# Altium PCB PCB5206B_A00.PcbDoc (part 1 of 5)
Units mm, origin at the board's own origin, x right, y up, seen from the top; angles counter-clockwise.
Board outline 115 x 60 mm, 6 copper layers (Top Layer, GND Layer 2, Signal Layer 3, Signal Layer 4, VCC Layer 5, Bottom Layer), stack 1.555 mm thick; 384 components, 267 nets, 1313 pads, 834 vias.
Unrouted connection lines stored in the file: 10.
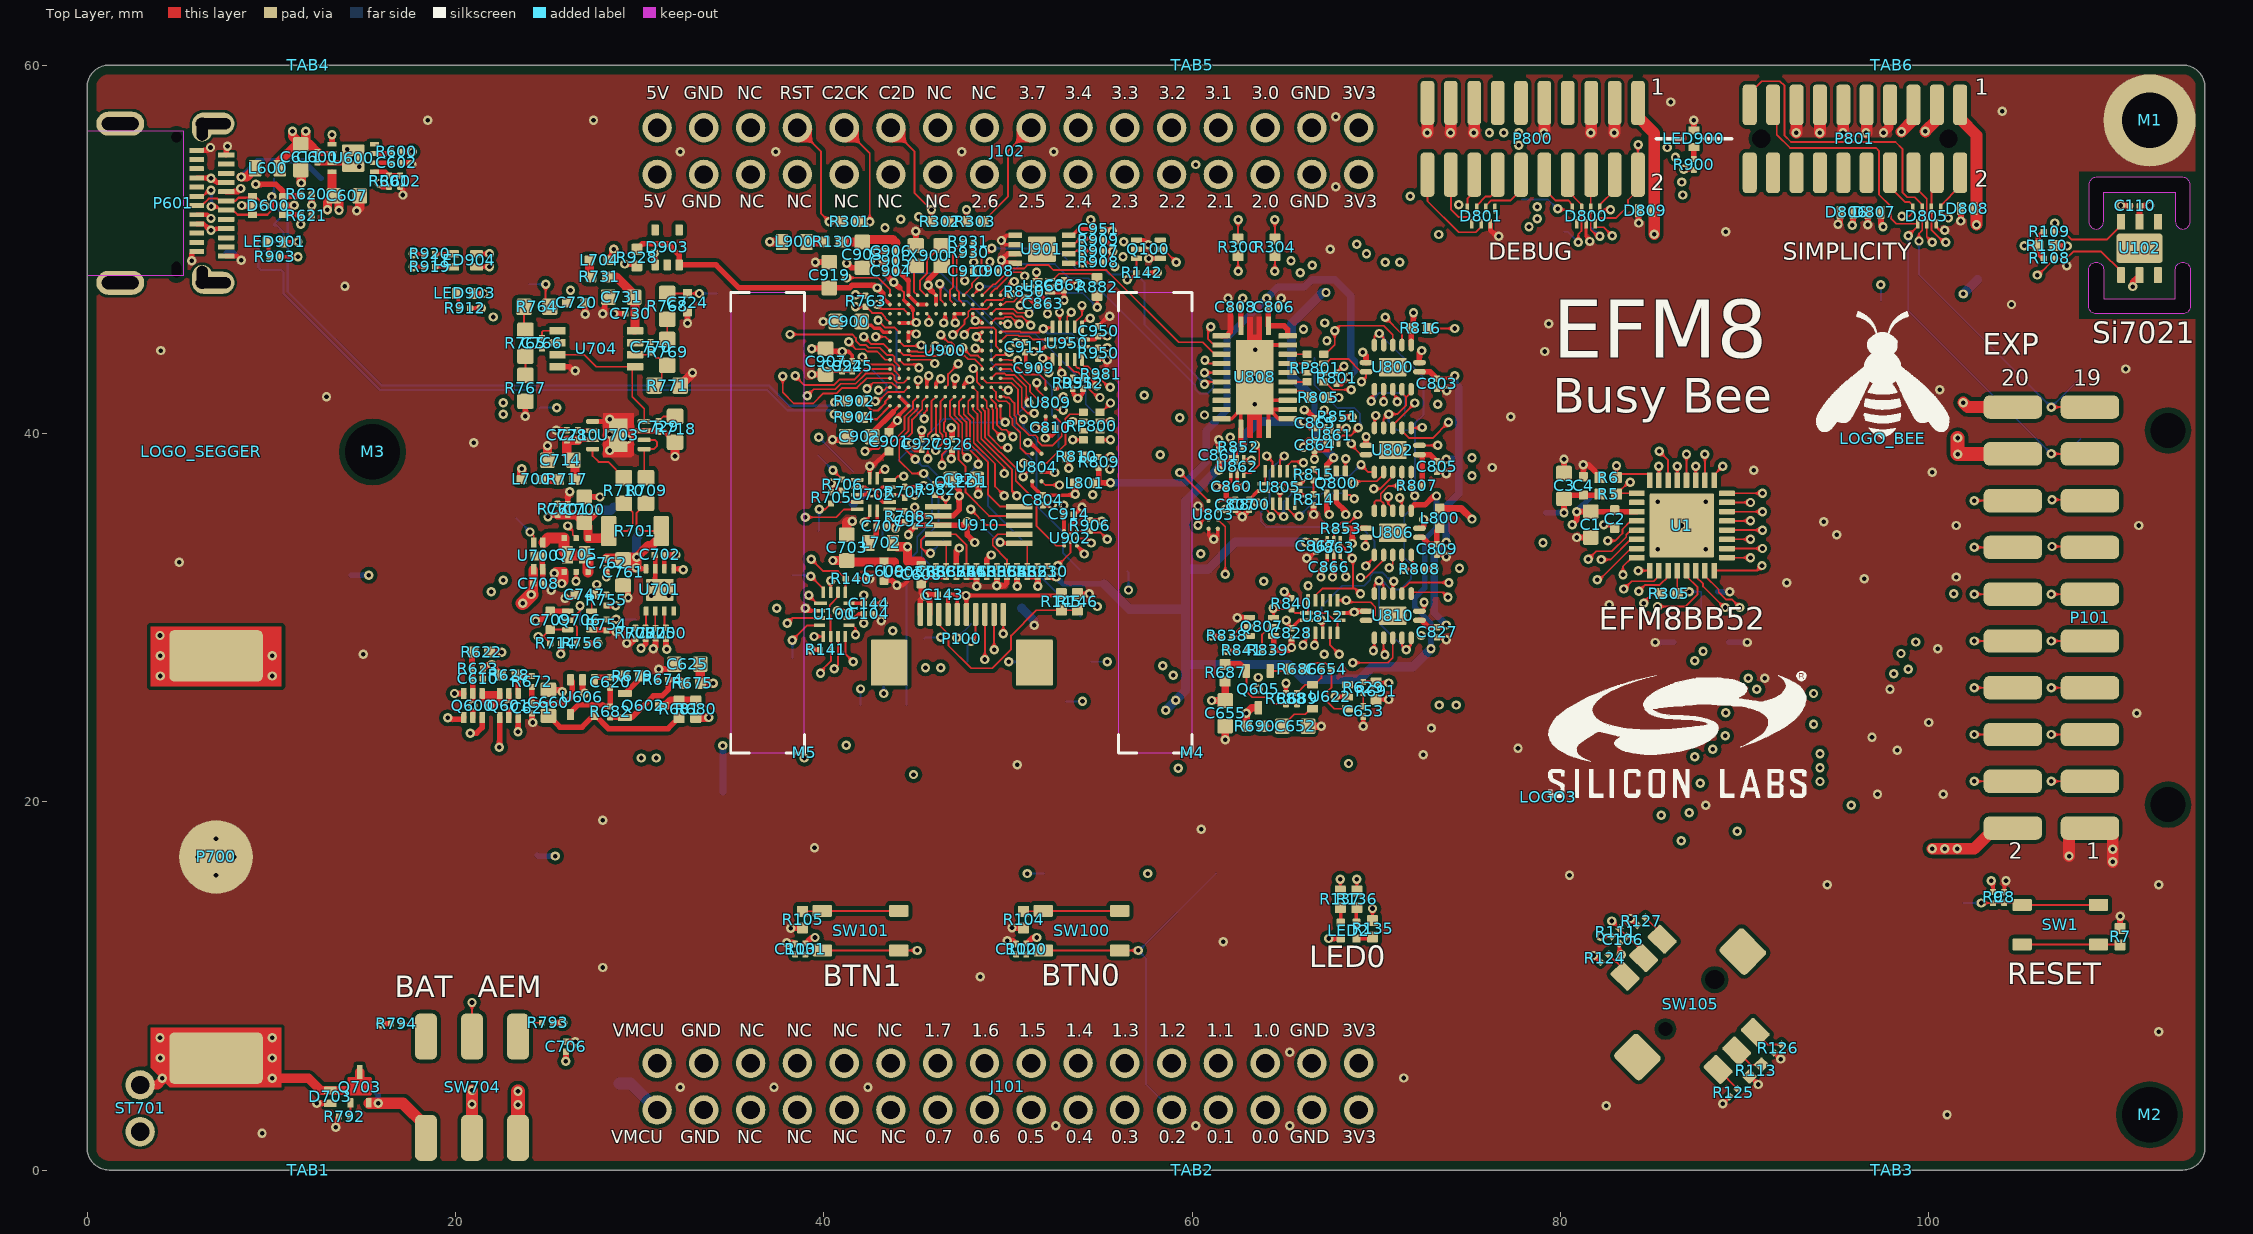
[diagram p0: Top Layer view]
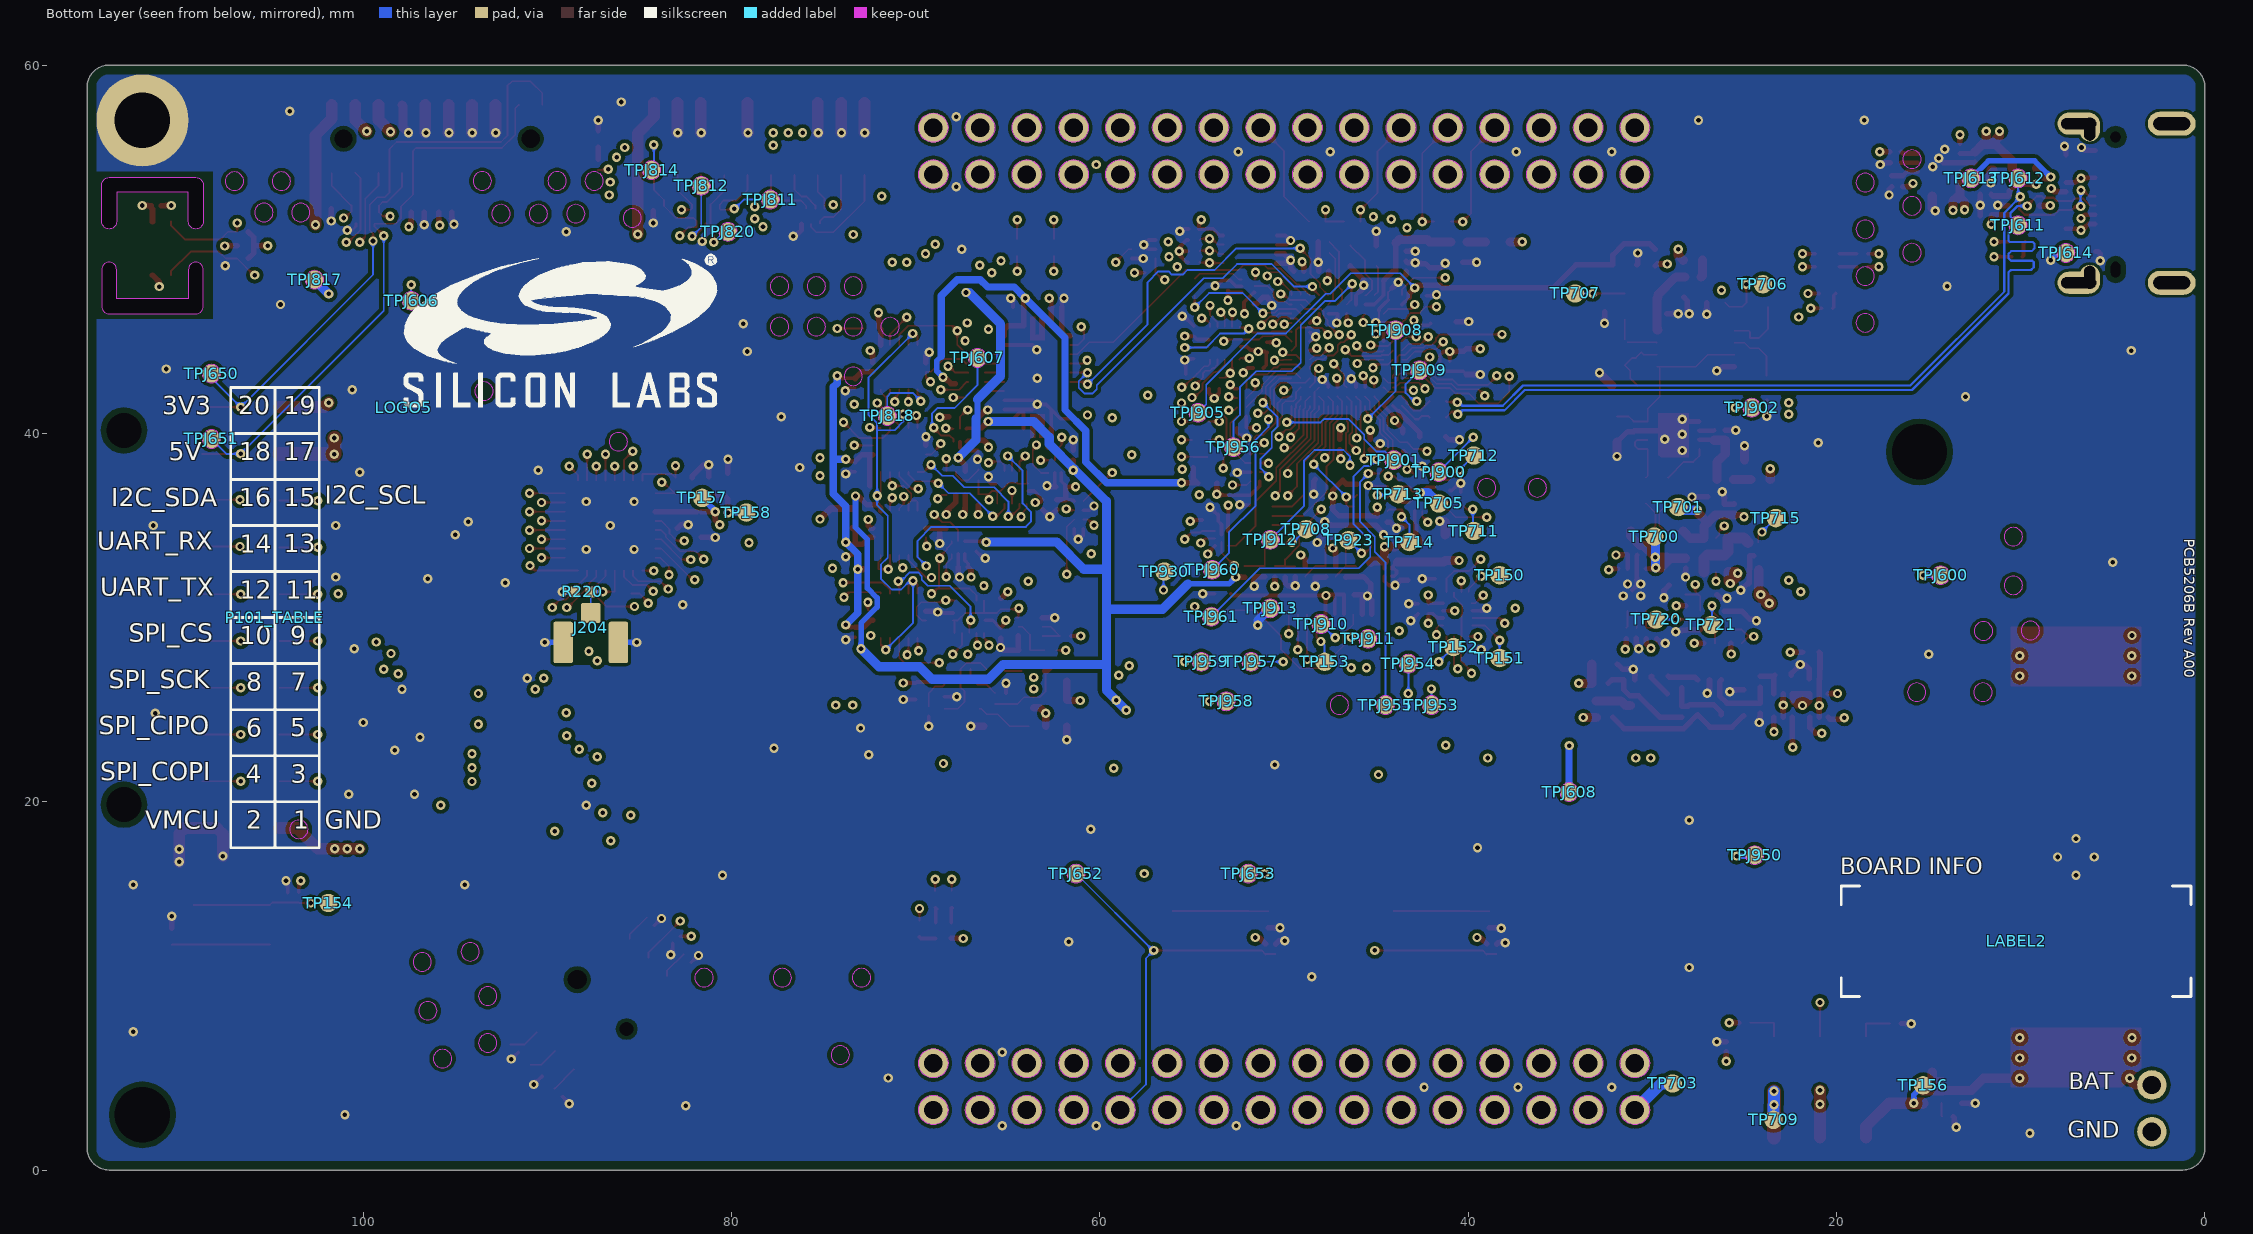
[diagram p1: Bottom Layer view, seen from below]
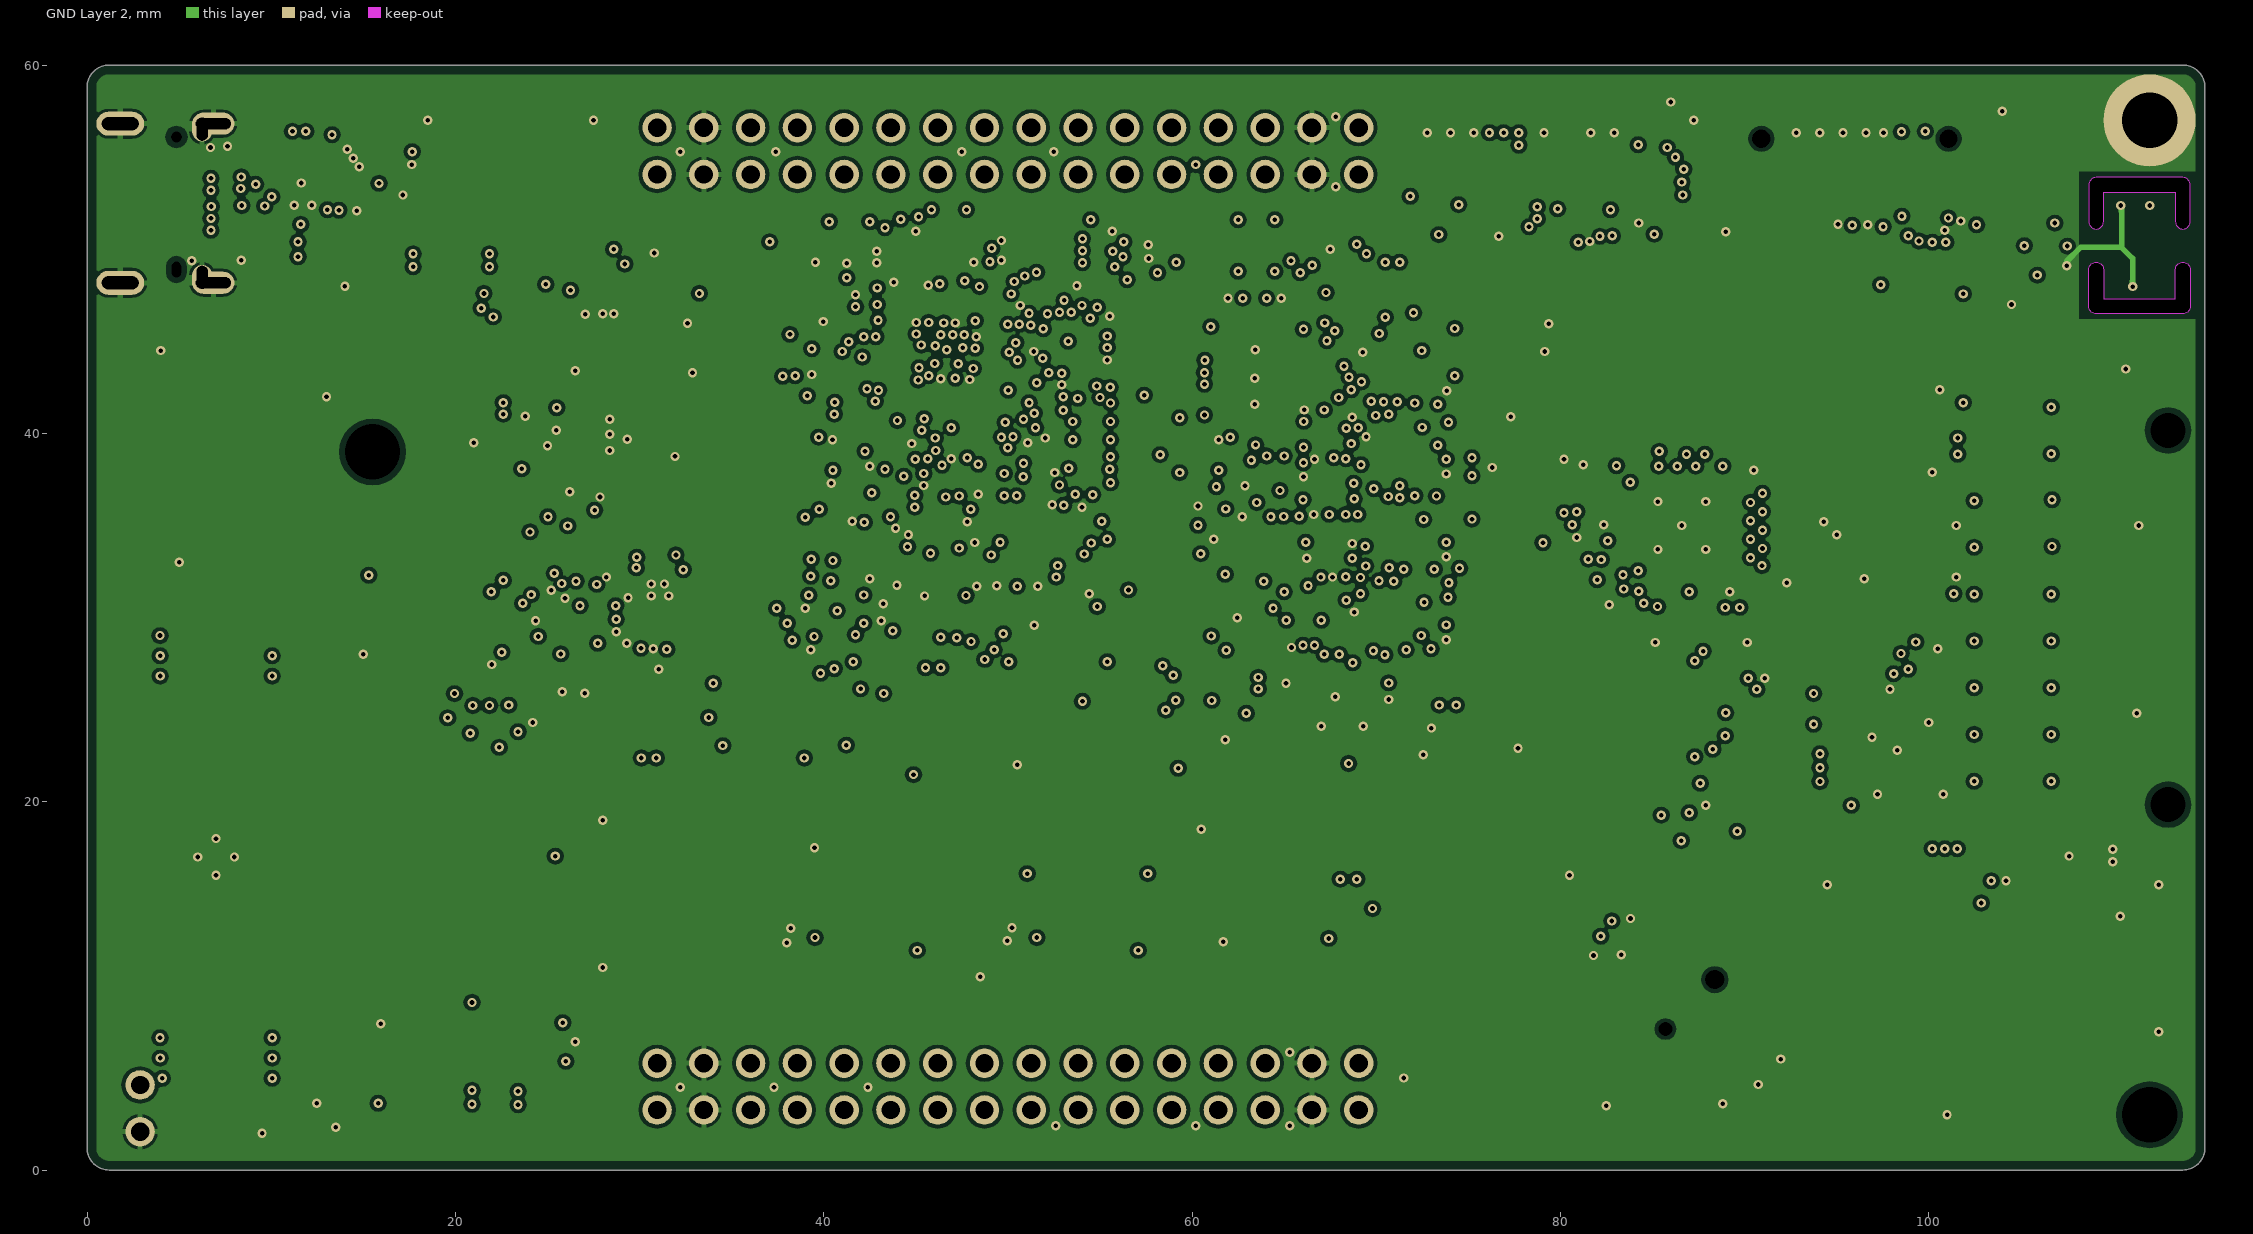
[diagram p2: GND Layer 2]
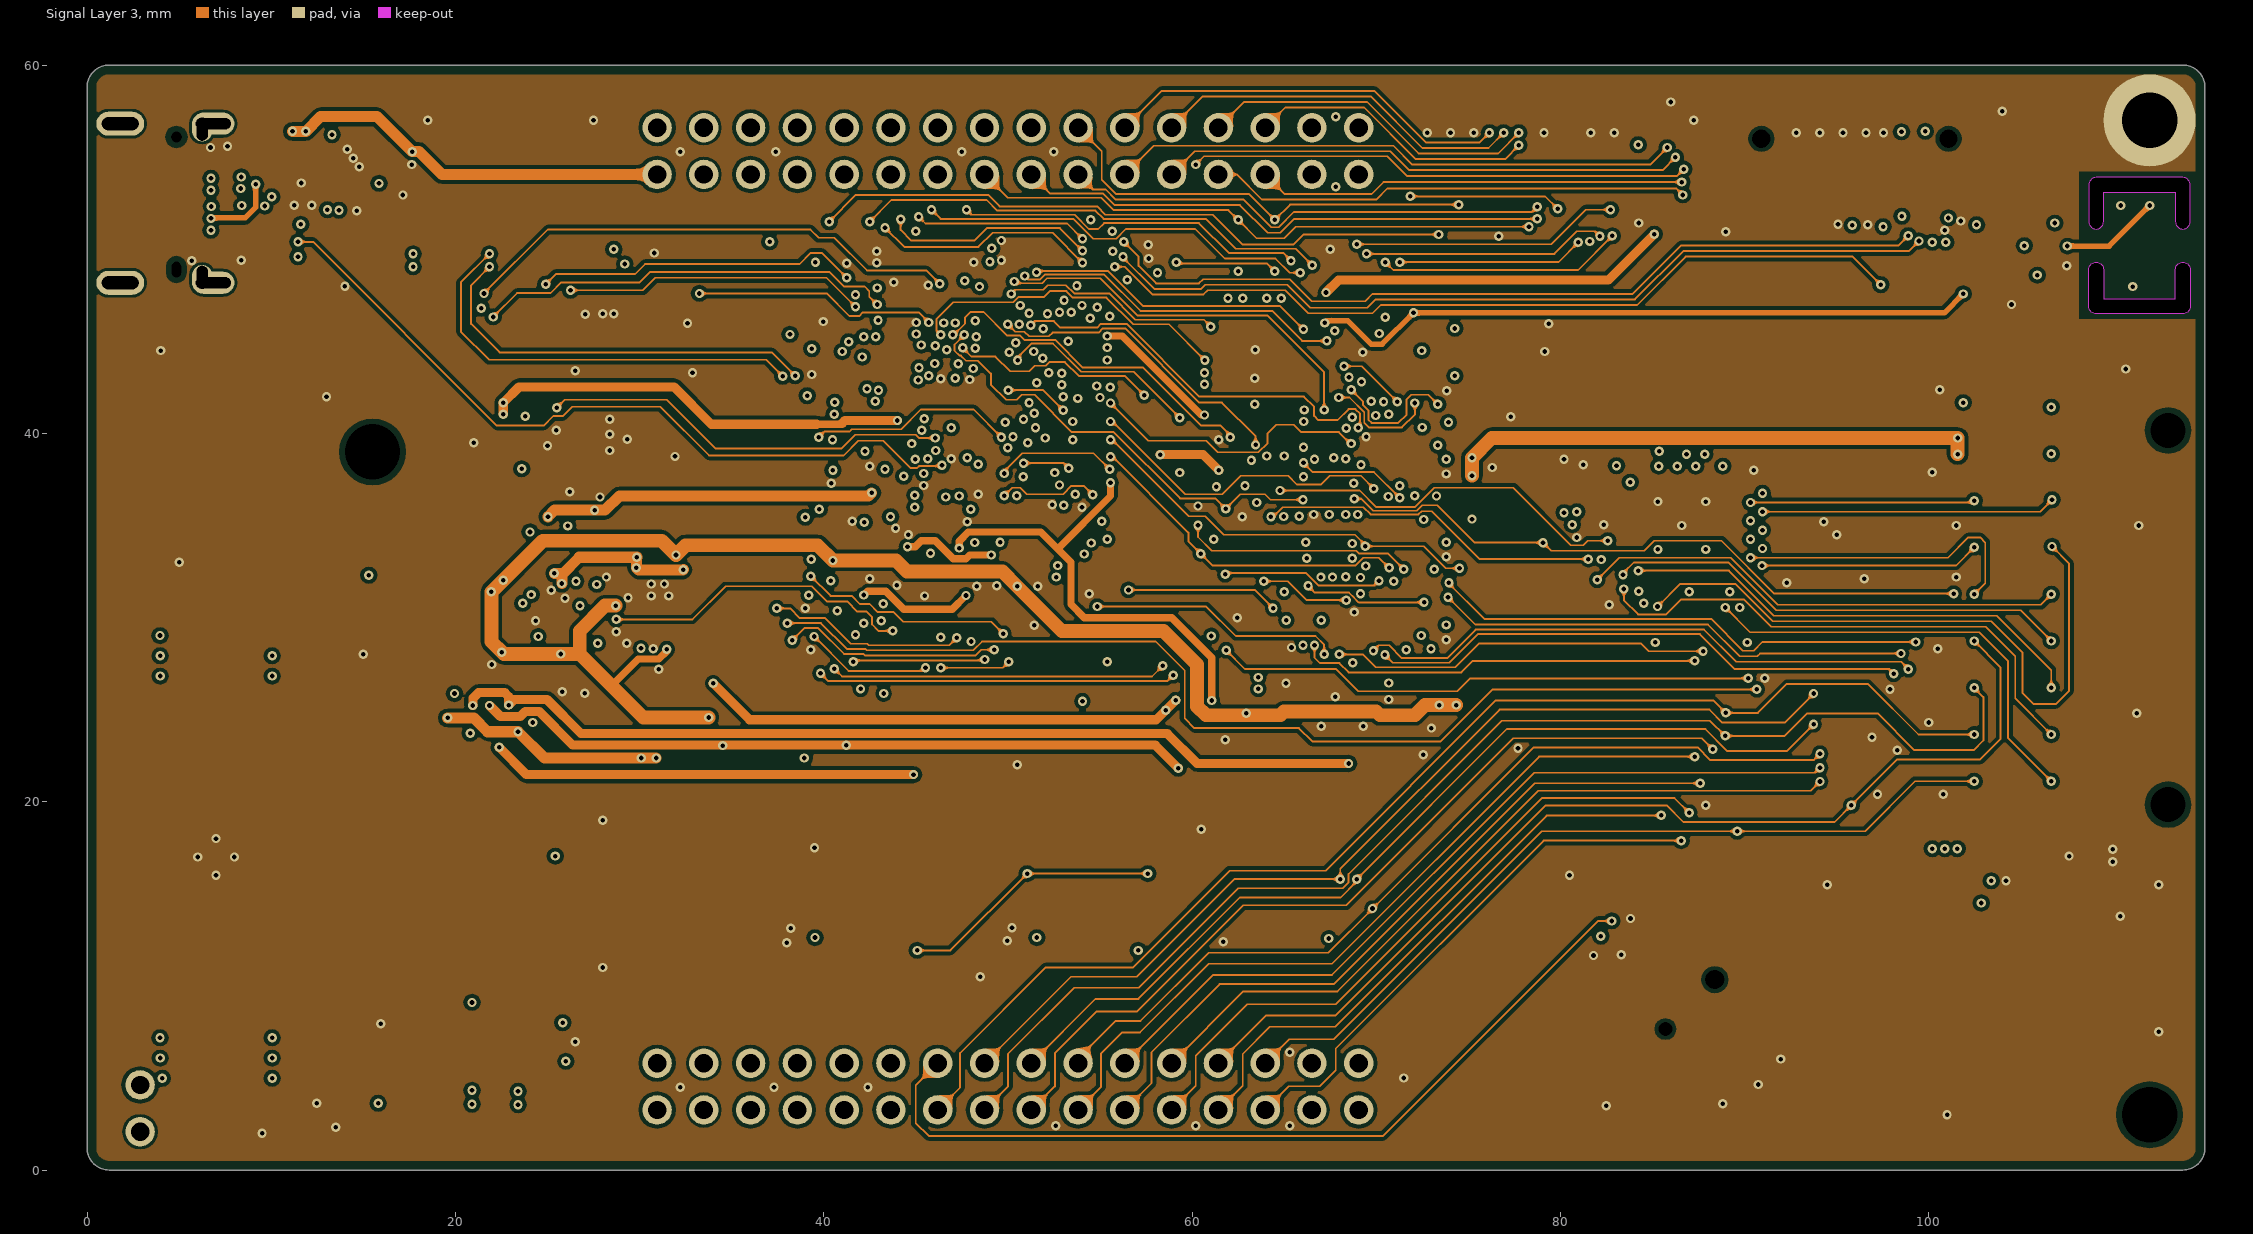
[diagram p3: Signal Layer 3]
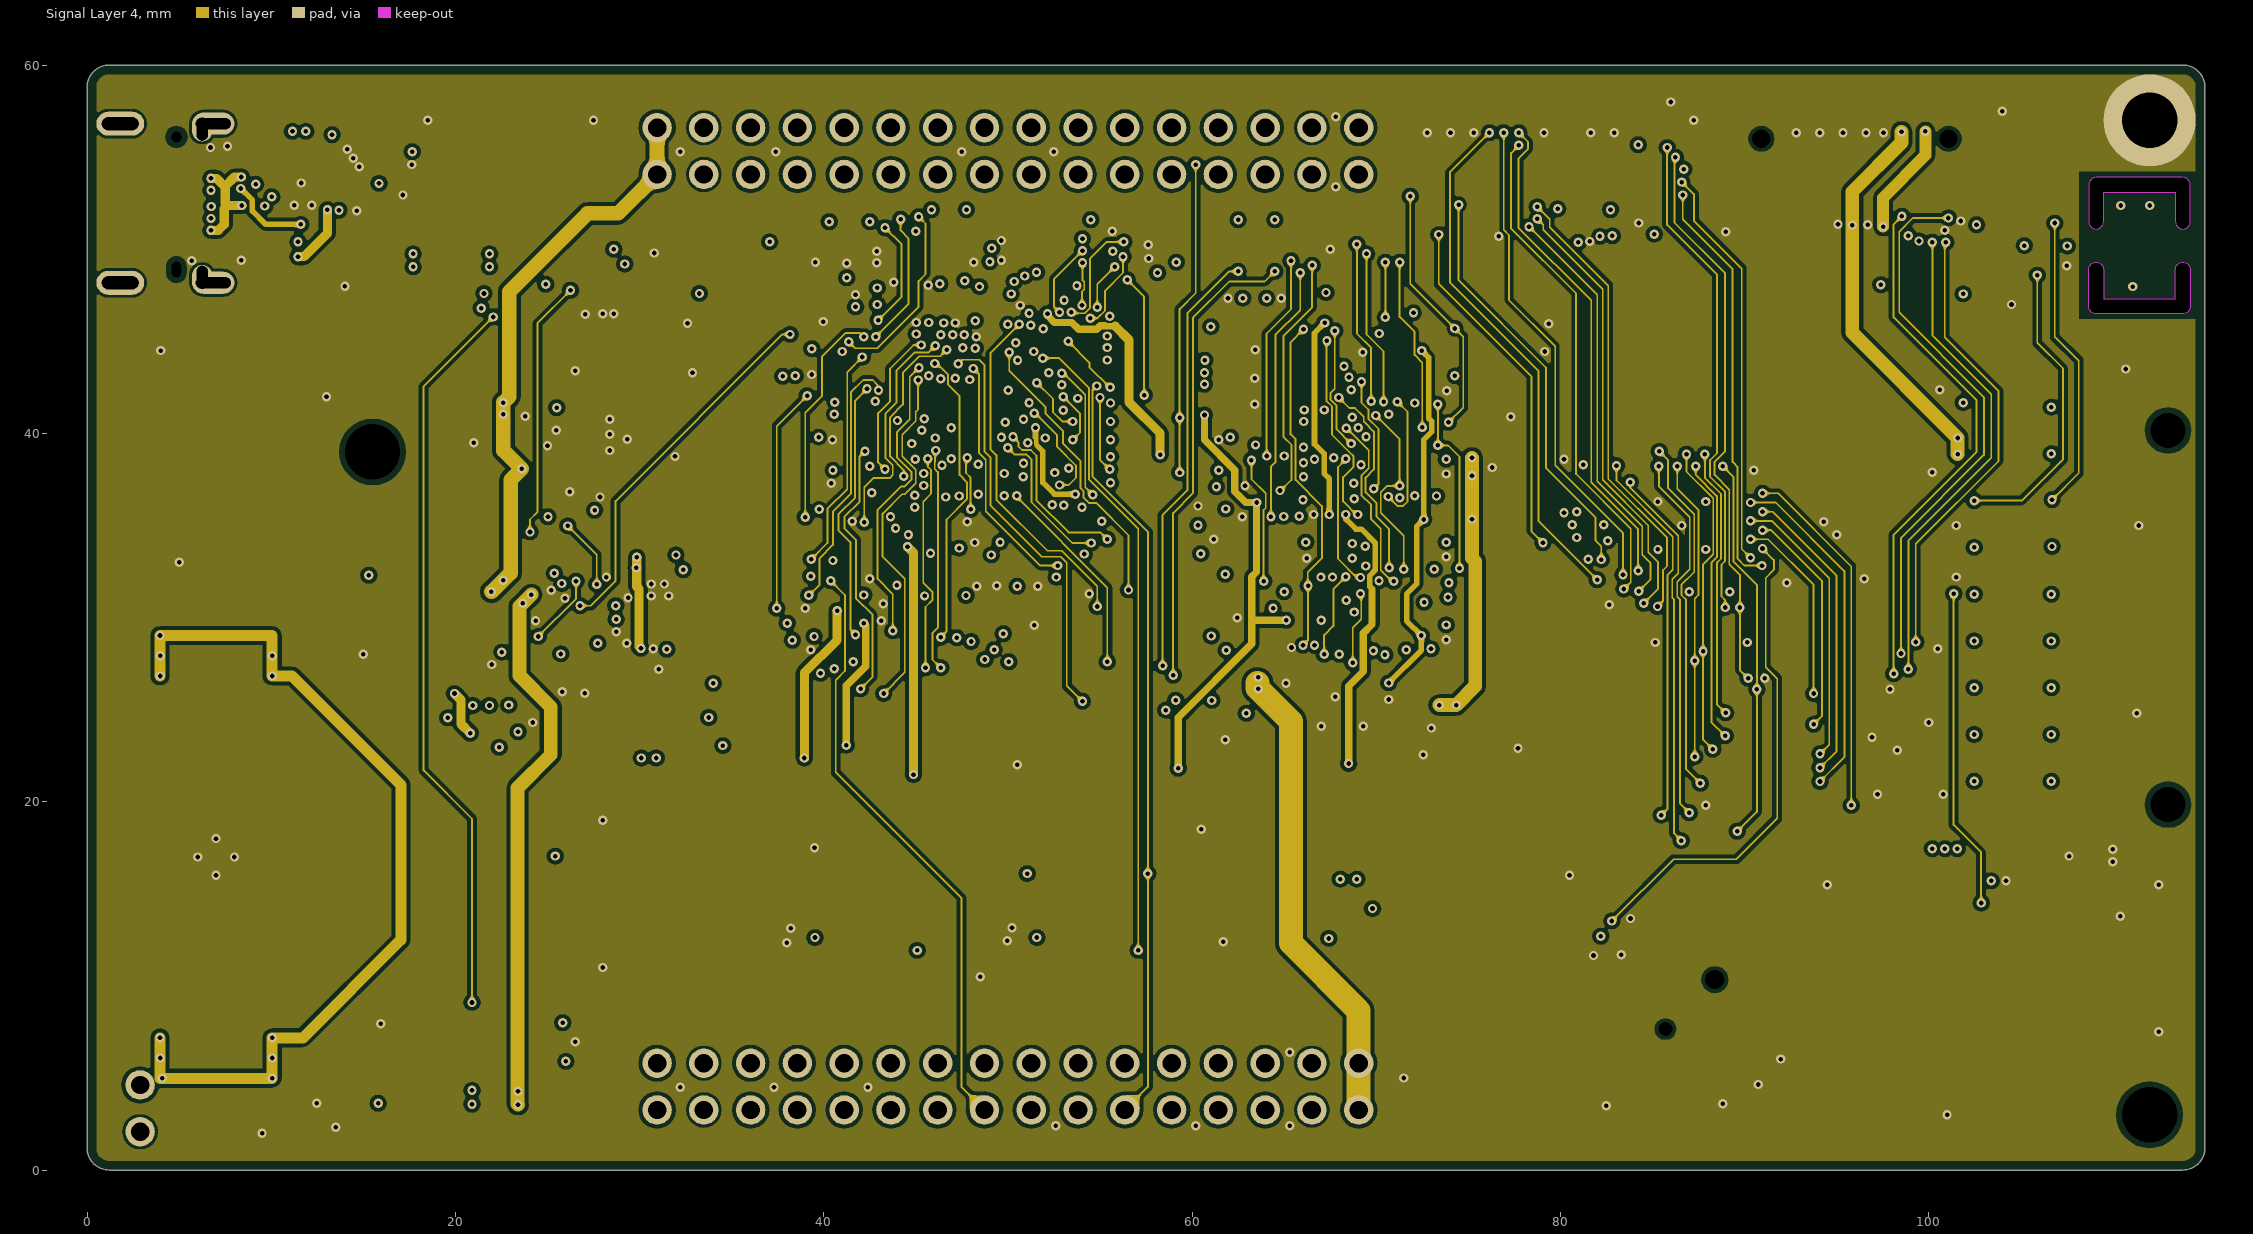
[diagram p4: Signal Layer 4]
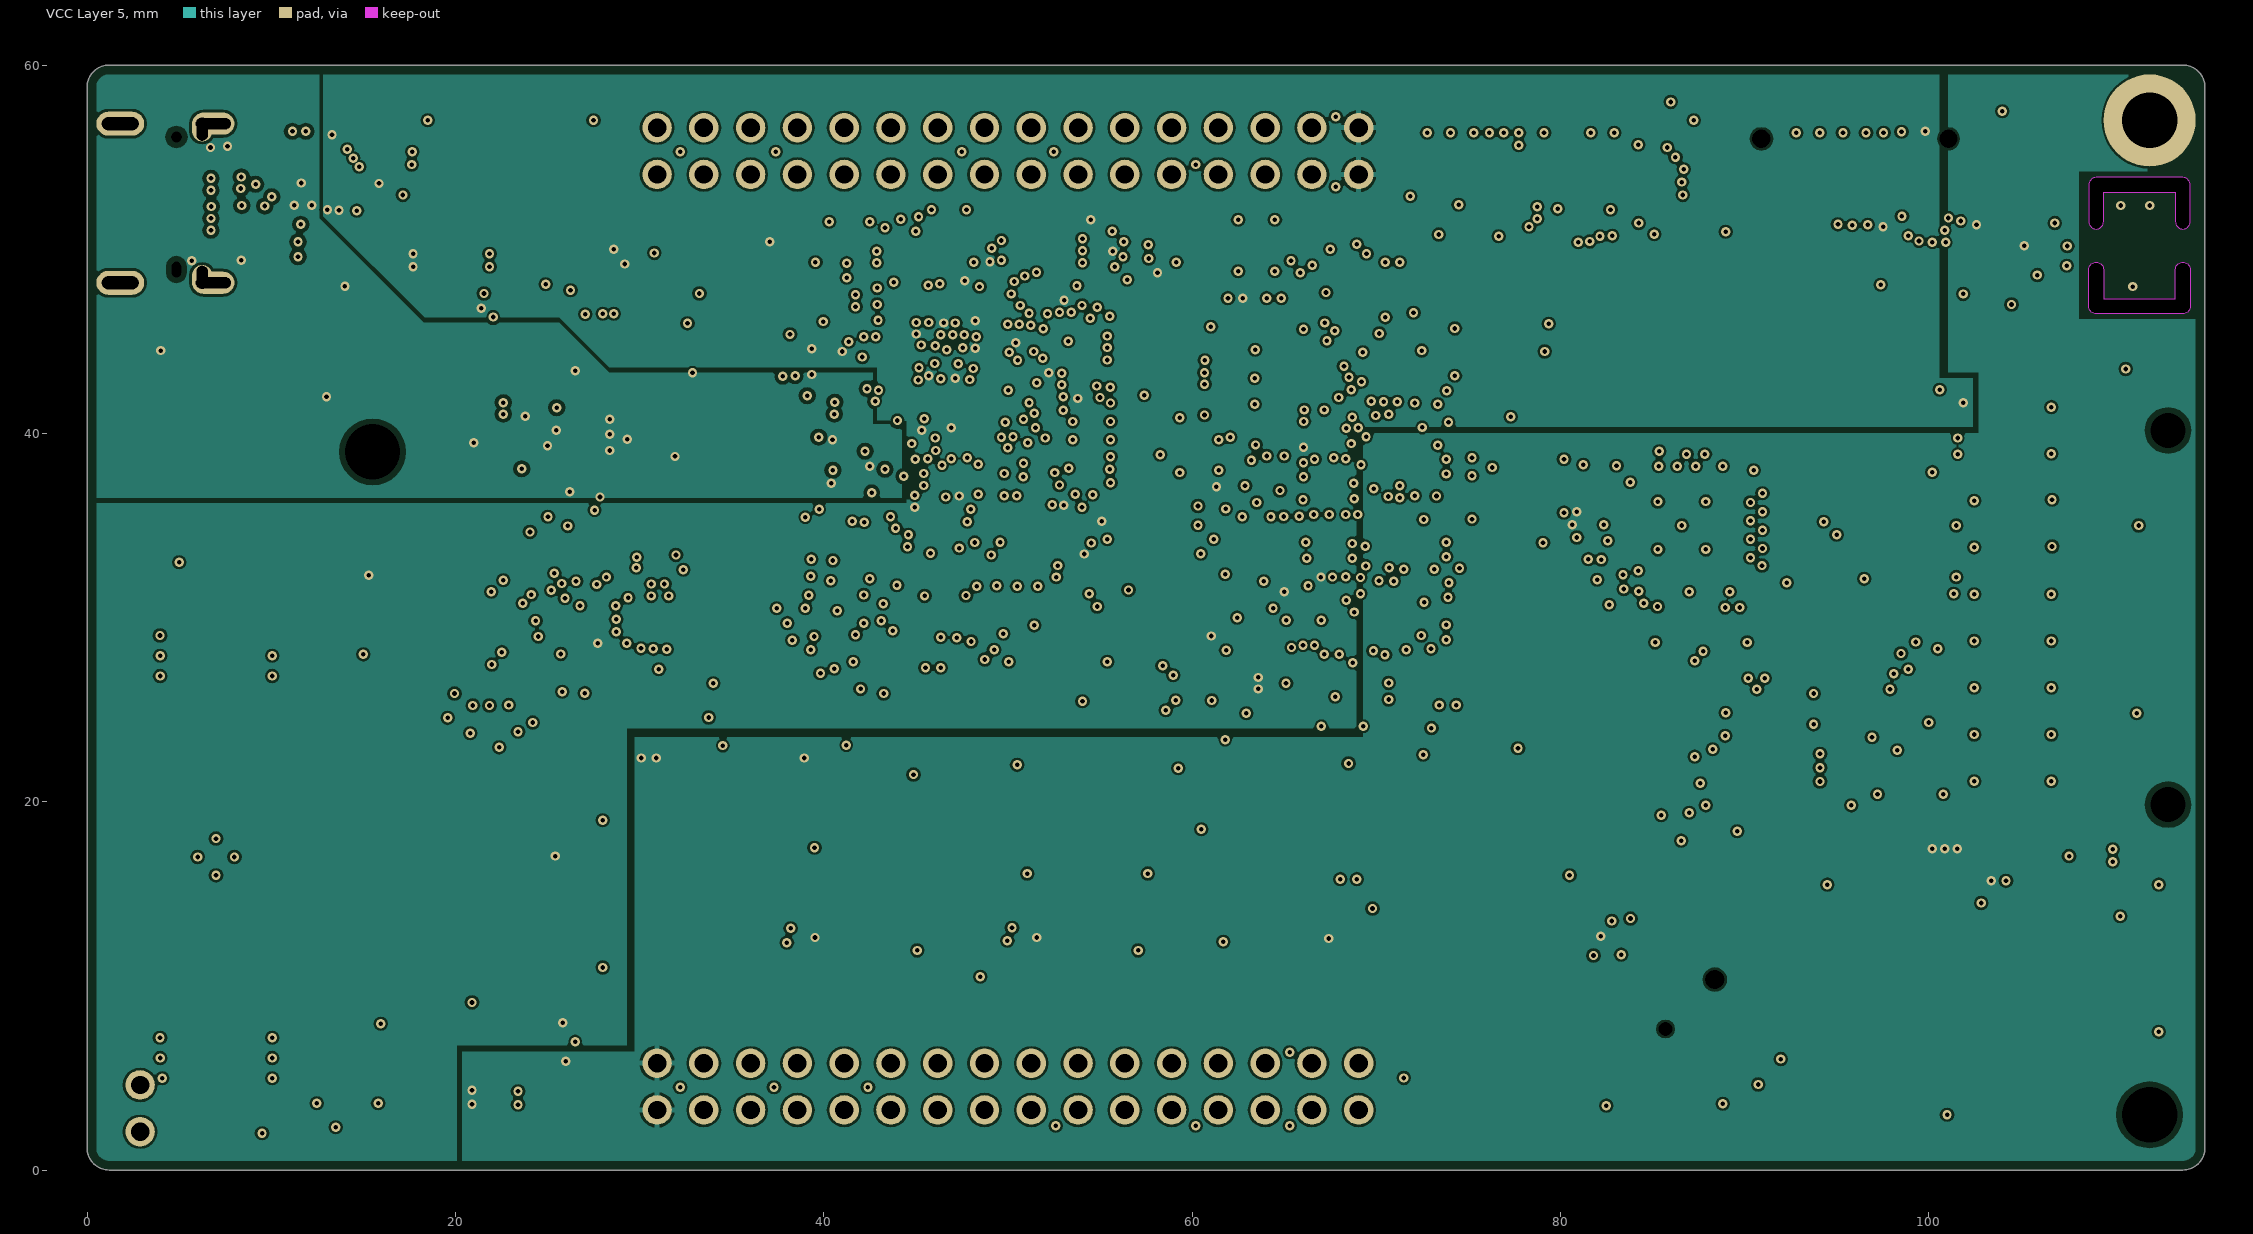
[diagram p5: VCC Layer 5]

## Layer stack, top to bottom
Top Solder: solder mask 0.03, Solder Resist, Dk 3.5
Top Layer: signal copper 0.035
Dielectric 1: prepreg 0.1, FR-4, Dk 4.2
GND Layer 2: signal copper 0.035
Dielectric 2: core 0.46, Core-009, Dk 4.2
Signal Layer 3: signal copper 0.035
Dielectric 3: prepreg 0.225, PP-006, Dk 4.2
Signal Layer 4: signal copper 0.035
Dielectric 4: core 0.46, Core-009, Dk 4.2
VCC Layer 5: signal copper 0.035
Dielectric  5: prepreg 0.1, FR-4, Dk 4.2
Bottom Layer: signal copper 0.035
Bottom Solder: solder mask 0.03, Solder Resist, Dk 3.5

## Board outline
0,1.2 0,58.8 cw(c1.2,58.8) 1.2,60 113.8,60 cw(c113.8,58.8) 115,58.8 115,1.2 cw(c113.8,1.2) 113.8,0 1.2,0 cw(c1.2,1.2)
cut-out: 108.7,53.5 108.7,51.5 ccw(c109.1,51.5) 109.1,51.1 ccw(c109.1,51.5) 109.5,51.5 109.5,53.1 113.4,53.1 113.4,51.5 ccw(c113.8,51.5) 113.8,51.1 ccw(c113.8,51.5) 114.2,51.5 114.2,53.5 ccw(c113.8,53.5) 113.8,53.9 109.1,53.9 ccw(c109.1,53.5)
cut-out: 108.7,46.9 108.7,48.9 cw(c109.1,48.9) 109.1,49.3 cw(c109.1,48.9) 109.5,48.9 109.5,47.3 113.4,47.3 113.4,48.9 cw(c113.8,48.9) 113.8,49.3 cw(c113.8,48.9) 114.2,48.9 114.2,46.9 cw(c113.8,46.9) 113.8,46.5 109.1,46.5 cw(c109.1,46.9)

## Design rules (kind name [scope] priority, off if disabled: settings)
BoardOutlineClearance BoardOutlineClearance_IGNORE_USB [HasFootprint('FCI_10137065_USB-C_RCPT') and IsKeepOut] p1: gap=0.5 ignorepadtopadclearanceinfootprint=FALSE except(0: Region-OutlineEdge Region-CavityEdge Region-CutoutEdge Region-SplitBarrior Region-SplitContinuation; 0.26: Arc-CutoutEdge Track-CutoutEdge SMDPad-CutoutEdge THPad-CutoutEdge Via-CutoutEdge Fill-CutoutEdge Poly-CutoutEdge Text-CutoutEdge; 0.4: THPad-OutlineEdge)
BoardOutlineClearance [Not HasFootprint('TAB50.5_T1.6_W2.4') or not HasFootprint('FCI_10137065_USB-C_RCPT')] p2: gap=0.5 ignorepadtopadclearanceinfootprint=FALSE except(0.26: Arc-CutoutEdge Track-CutoutEdge SMDPad-CutoutEdge THPad-CutoutEdge Via-CutoutEdge Fill-CutoutEdge Poly-CutoutEdge Region-CutoutEdge Text-CutoutEdge; 0.4: THPad-OutlineEdge)
Clearance Clearance_NPL [(ObjectKind = 'Pad') And (Layer = 'MultiLayer') And (PadIsPlated = 'False')] p1: gap=0.3 ignorepadtopadclearanceinfootprint=FALSE
Clearance Clearance_Polygon_GND [InNet('GND') and InPolygon] p2: gap=0.2 ignorepadtopadclearanceinfootprint=FALSE
Clearance Clearance_Polygon_General [InPolygon] p3: gap=0.125 ignorepadtopadclearanceinfootprint=FALSE
Clearance Clearance_Via_Track [IsVia vs IsTrack] p4: gap=0.089 ignorepadtopadclearanceinfootprint=FALSE except(0: Arc-Hole Track-Hole SMDPad-Hole THPad-Hole Via-Hole Fill-Hole Poly-Hole Region-Hole Text-Hole)
Clearance [All] p5: gap=0.1 ignorepadtopadclearanceinfootprint=FALSE
ComponentClearance ComponentClearance_IGNORE [HasFootprint('TESTJIGG_PCB4002_M14') OR HasFootprint('TAB50.5_T1.6_W2.4') OR HasFootprint('TP_6.0X6.0_MILLOUT_5.0X5.0_TH') Or InComponent('M1')] p1: gap=0 collisioncheckmode=3 verticalgap=0 showdistances=FALSE
ComponentClearance [All] p2: gap=0.2 collisioncheckmode=3 verticalgap=0.254 showdistances=FALSE
DiffPairsRouting DiffPairsRouting_90OHM [InDifferentialPair('USB_90') or InDifferentialPair('USB_90_U900')] p1: maxlimit=0.254 minlimit=0.12 mostfreqgap=0.254 toplayer_maxgap=0.12 toplayer_prefgap=0.12 toplayer_minwidth=0.12 toplayer_maxwidth=0.12 toplayer_prefwidth=0.12 bottomlayer_maxgap=0.12 bottomlayer_prefgap=0.12 bottomlayer_minwidth=0.12 bottomlayer_maxwidth=0.12 bottomlayer_prefwidth=0.12 impedanceprofiledriven=TRUE impedanceprofileid={B4300C99-598D-4438-91CE-854F904B181D} impedanceprofilevalue=90.000000 maxuncoupledlength=50
HoleSize [All] p1: absolutevalues=TRUE maxlimit=10 minlimit=0.1 maxpercent=80.000 minpercent=20.000
HoleToHoleClearance HoleToHoleClearance_general [Not InComponent('P601')] p1: gap=0.254 allowstackedmicrovias=TRUE
MatchedLengths [All] p1: tolerance=0.2 checknetsindiffpair=TRUE checkdiffpairvsdiffpair=FALSE checkxsignals=FALSE checkothers=FALSE
MinimumSolderMaskSliver MinimumSolderMaskSliver_IGNORE [InComponent('LOGO*') vs InComponent('LOGO*')] p1: minsoldermaskwidth=0
MinimumSolderMaskSliver [All] p2: minsoldermaskwidth=0.1
PolygonConnect PolygonConnect_Direct_Connect [InComponent('M1') or InComponent('J1') or InComponent('P700')] p1: connectstyle=Direct reliefconductorwidth=0.33 reliefentries=4 polygonreliefangle="90 Angle" airgapwidth=0.152
PolygonConnect PolygonConnect_IGNORE_GND_FILL [IsThruPin vs InNet('GND') and not OnLayer('GND Layer 2')] p2: connectstyle=NoConnect reliefconductorwidth=0.3 reliefentries=4 polygonreliefangle="90 Angle" airgapwidth=0.15
PolygonConnect PolygonConnect_general [All] p3: thpad.connectstyle=Relief thpad.reliefconductorwidth=0.3 thpad.reliefentries=4 thpad.polygonreliefangle="90 Angle" thpad.airgapwidth=0.15 smdpad.connectstyle=NoConnect smdpad.reliefconductorwidth=0.33 smdpad.reliefentries=4 smdpad.polygonreliefangle="90 Angle" smdpad.airgapwidth=0.15 via.connectstyle=Direct via.reliefconductorwidth=0.33 via.reliefentries=4 via.polygonreliefangle="90 Angle" via.airgapwidth=0.127
RoutingVias RoutingVias_Through [InDrillLayerPair('Top Layer - Bottom Layer')] p1: holewidth=0.25 width=0.508 viastyle="Through Hole" minholewidth=0.25 minwidth=0.508 maxholewidth=1 maxwidth=1.5 useviatemplates=TRUE viatemplateguid#1={08D43F0E-9906-4177-A4FE-1C96C0EB29F0} viatemplatename#1=v51h25m0mx0(1)
ShortCircuit ShortCircuit_General [All] p1: allowed=FALSE
SilkToSilkClearance [All] p1: silktosilkclearance=0.102
SilkToSolderMaskClearance [IsPad] p1: minsilkscreentomaskgap=0.102 clearancetoexposedcopper=TRUE
SolderMaskExpansion [All] p1: expansion=0.05 istentingtop=FALSE
UnRoutedNet [All] p1: checkbadconnections=TRUE
Width [All] p1: maxlimit=5.08 minlimit=0.1 preferedwidth=0.1 minimp=50.000000 maximp=50.000000 favimp=50.000000
21 further rules are at their usual default settings.

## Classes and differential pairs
net class USB_90: N16942491 N16942503 USB_DM USB_DP
differential pair USB_90_U900: +N16942503 -N16942491
differential pair USB_90: +USB_DP -USB_DM
differential pair ETH_RX: +"" -""
differential pair ETH_TX: +"" -""
differential pair USB: +"" -""

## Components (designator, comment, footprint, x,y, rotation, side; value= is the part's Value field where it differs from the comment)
C1 "10U" C0603 81.65,35.05 r270 top
C2 "100N" C0402 82.95,35.35 r270 top
C3 "10U" C0603 80.2,37.15 r90 top
C4 "100N" C0402 81.25,37.15 r90 top
C8 "100N" C0201 104.1,14.8 r90 top
C102 "1N" C0201 50.45,12 r90 top
C103 "1N" C0201 38.45,12 r90 top
C104 "100N" C0201 42.45,30.2 r0 top
C106 "1N" C0201 83.4,12.5 r225 top
C110 "100N" C0201 111.2,52.35 r180 top
C143 "100N" C0201 46.475,31.25 r180 top
C144 "100N" C0201 42.45,30.75 r0 top
C600 "100N" C0201 12.5,55 r270 top
C602 "33N" C0201 16.8,54.7 r0 top
C607 "10U" C0603 14.1,52.9 r0 top
C608 "1U" C0402 45.3,32.325 r270 top
C609 "1U" C0402 43.275,32.525 r270 top
C610 "1N" C0201 21.2,26.675 r0 top
C611 "10U" C0603 11.6,55 r270 top
C620 "100P" C0201 28.4,26.475 r90 top
C621 "100N" C0201 24.15,25.075 r270 top
C625 "10U" C0603 32.6,27.475 r180 top
C632 "10N" C0201 51.05,32.5 r270 top
C635 "10N" C0201 49.4,32.5 r270 top
C638 "10N" C0201 46.1,32.5 r270 top
C641 "10N" C0201 47.75,32.5 r270 top
C652 "10U" C0603 65.6,24.1 r0 top
C653 "100N" C0201 69.3,24.9 r270 top
C654 "100P" C0201 67.3,27.2 r0 top
C655 "10U" C0603 61.8,24.8 r270 top
C660 "10U" C0603 25.05,25.375 r90 top
C700 "10U" C0603 27,35.85 r90 top
C701 "100N" C0201 26.1,35.875 r90 top
C702 "100N" C0201 31.1,33.4 r180 top
C703 "10U" C0603 41.25,33.8 r90 top
C705 "33N" C0201 30.875,29.15 r270 top
C706 "100N" C0201 26,6.7 r90 top
C707 "100N" C0201 43.15,34.95 r0 top
C708 "100N" C0201 24.5,31.85 r0 top
C709 "100P" C0402 25.15,29.85 r90 top
C710 "100N" C0201 26.65,39.9 r90 top
C714 "10U" C0603 25.7,38.55 r180 top
C720 "1N" C0402 26.55,47.1 r0 top
C724 "1N" C0402 32.6,47.1 r270 top
C728 "100N" C0201 26.05,39.9 r90 top
C729 "2N2" C0201 31.025,40.375 r270 top
C730 "100N" C0201 29.5,46.5 r180 top
C731 "10U" C0603 29,47.4 r180 top
C747 "100P" C0402 27,31.25 r180 top
C761 "10U" C0603 29.1,32.45 r270 top
C762 "100N" C0201 28.2,32.95 r270 top
C766 "10P" C0201 24.7,44.9 r90 top
C770 "10P" C0201 30.6,44.675 r90 top
C800 "100N" C0201 63.1,36.125 r270 top
C803 "100N" C0201 73.3,42.7 r270 top
C804 "100N" C0201 51.9,36.375 r270 top
C805 "100N" C0201 73.3,38.2 r270 top
C806 "100N" C0201 64.45,46.85 r0 top
C807 "100N" C0201 62.35,36.125 r270 top
C808 "100N" C0201 62.35,46.85 r180 top
C809 "100N" C0201 73.3,33.7 r270 top
C810 "100N" C0201 52.3,40.3 r0 top
C827 "100N" C0201 73.3,29.2 r270 top
C828 "100N" C0201 65.4,29.15 r270 top
C860 "100N" C0201 62.125,37.1 r0 top
C861 "100N" C0201 61.45,38.825 r90 top
C862 "100N" C0201 53.05,48.05 r90 top
C863 "100N" C0201 51.9,47.05 r180 top
C864 "100N" C0201 66.65,39.35 r270 top
C865 "100N" C0201 66.65,40.55 r90 top
C866 "100N" C0201 67.425,32.725 r0 top
C867 "100N" C0201 66.725,33.875 r270 top
C900 "1U" C0603 41.35,46.075 r180 top
C901 "1U" C0402 43.55,39.55 r270 top
C902 "4U7" C0603 41.925,39.825 r180 top
C903 "10U" C0603 42.1,49.7 r270 top
C904 "10N" C0201 43.65,48.8 r180 top
C905 "10N" C0201 43.65,49.35 r180 top
C906 "10N" C0201 43.65,49.9 r180 top
C907 "4U7" C0603 40.1,43.9 r270 top
C908 "100N" C0201 49.2,48.8 r0 top
C909 "100N" C0201 51.4,43.55 r180 top
C910 "100N" C0201 47.85,48.8 r0 top
C911 "100N" C0201 50.925,44.675 r270 top
C914 "100N" C0201 53.3,35.6 r0 top
C919 "10U" C0603 40.3,48.6 r90 top
C921 "4U7" C0603 47.6,37.5 r0 top
C922 "100N" C0201 44.95,35.225 r270 top
C924 "100N" C0201 41,43.65 r270 top
C925 "100N" C0201 41.55,43.65 r270 top
C926 "100N" C0201 46.975,39.4 r270 top
C927 "100N" C0201 45.325,39.4 r270 top
C950 "10N" C0201 54.9,45.55 r90 top
C951 "100N" C0201 54.9,51.1 r0 top
D600 "DT1446-04" SOT563_DIODES 9.825,52.375 r180 top
D703 "ESD" X2-DFN1006-2 13.2,3.975 r270 top
D800 "PUSB3AB6" DFN2111-7_M050_1.2X2.1_NXP 81.4,51.8 r270 top
D801 "PUSB3AB6" DFN2111-7_M050_1.2X2.1_NXP 75.7,51.8 r270 top
D805 "PUSB3AB6" DFN2111-7_M050_1.2X2.1_NXP 99.9,51.8 r270 top
D806 "ESD" X2-DFN1006-2 95.55,52 r180 top
D807 "ESD" X2-DFN1006-2 97.05,52 r180 top
D808 "ESD" X2-DFN1006-2 102.1,52.209 r180 top
D809 "ESD" X2-DFN1006-2 84.6,52.1 r180 top
D903 "LM4040C30IDCK" SC70-5 31.5,50.1 r90 top
J101 "HEADER_2X16_2.54MM_TH" HDR_M254-2X16 50,4.532 r0 top locked
J102 "HEADER_2X16_2.54MM_TH" HDR_M254-2X16 50,55.332 r0 top locked
J204 "U.FL" HRS_U.FL-R-SMT_123 87.65,28.65 r0 bottom
L600 "742792662" COIL_WURTH_CBF_0603 9.8,54.4 r0 top
L700 "742792796" COIL_0402 24.125,37.5 r0 top
L702 "74279266" COIL_WURTH_CBF_0603 43.1,34.05 r180 top
L704 "742792796" COIL_0402 27.8,49.4 r180 top
L800 "742792796" COIL_0402 73.45,35.4 r270 top
L801 "742792796" COIL_0402 54.175,37.3 r180 top
L900 "74279266" COIL_WURTH_CBF_0603 38.4,50.4 r0 top
LABEL2 "Comment" LABEL_4CORNERS_19.0X6.0 10.25,12.425 r180 bottom
LED2 "RGB" LED_LUMEX_SML-LX0404-4 68.5,13 r0 top
LED900 "YELLOW" LED_0402_CAT2 87.25,56 r90 top
LED901 "BLUE" LED_0402_CAT2 10.2,50.4 r0 top
LED903 "RED" LED_0402 20.5,47.6 r180 top
LED904 "LED_G_R" LED_AVAGO_HSMF-C165-4 20.5,49.4 r0 top
LOGO3 "Comment" LOGO_SILABS_W14.0_SILK 79.35,20.25 r0 top locked
LOGO5 "Comment" LOGO_SILABS_W18.0 97.8,41.4 r180 bottom
LOGO_BEE "Comment" LOGO_BEE_H7.0 97.5,39.7 r0 top locked
LOGO_SEGGER "Comment" LOGO_SEGGER_10.0X5.0_SM 6.2,39 r0 top locked
M1 "HOLE_PTH_3MM" HOLE_3.0_5.0_PL 112,57 r0 top locked
M2 "Comment" HOLE_3.0_NPL 112,3 r0 top locked
M3 "Comment" HOLE_3.0_NPL 15.5,39 r90 top locked
M4 "Comment" ADHESIVE_PAD_25.0X4.0 60,22.65 r90 top locked
M5 "Comment" ADHESIVE_PAD_25.0X4.0 38.95,22.65 r90 top locked
OLED1 "Comment" OLED_LS013B7DH03 47.5,37.35 r0 top locked
P100 "L-KLS1-242D-1.2-10" WCON_5142_FPC_0.5-10 45.25,30.175 r0 top locked
P101 "HEADER_2X10_2.54MM_TH" WCON_1125B-1210_HOR_PEG-2X10 113,19.84 r90 top locked
P101_TABLE "Comment" LABEL_P101_PIN_TABLE_SL 104.8,30 r180 bottom locked
P601 "AMPH_10137065" FCI_10137065_USB-C_RCPT 4.85,52.5 r270 top
P700 "CR2032" BAT_HOLD_MPD_BK-912_CR2032 7,17 r270 top locked
P800 "HEADER_DEBUG_ETM" WCON_3132_HDR_M127_SMD-2X10 78.5,56 r180 top locked
P801 "HEADER_2X10_1.27MM_SMD" HDR_SULLINS_M127_PEG-2X10 101.08,56 r180 top locked
Q100 "DMN5L06VK" SOT563 57.625,50 r180 top
Q600 "BSS84" SOT563 20.95,25.225 r90 top
Q601 "DMN5L06VK" SOT563 22.9,25.225 r90 top
Q602 "BC846BWT1G" SC70_123 30.2,25.225 r0 top
Q605 "BC846BWT1G" SC70_123 63.6,26.1 r270 top
Q703 "DMG3415" X2-DFN2015-3_DIODES 14.8,4.55 r90 top
Q705 "SiA975DJ" POWERPAK_SC70-6 26.55,33.4 r90 top
Q706 "DMN5L06VK" SOT563 26.75,29.85 r180 top
Q800 "DMN5L06VK" SOT563 67.825,37.3 r270 top
Q807 "DMN5L06VK" SOT563 63.775,29.5 r180 top
R5 "0R" R0402 82.6,36.7 r0 top
R6 "0R" R0402 82.6,37.6 r0 top
R7 "100R" R0402 110.4,12.675 r270 top
R9 "1K" R0201 103.5,14.8 r270 top
R100 "1M" R0201 51,12 r90 top
R101 "1M" R0201 39,12 r90 top
R104 "100R" R0402 50.85,13.6 r270 top
R105 "100R" R0402 38.85,13.6 r270 top
R108 "4K7" R0201 106.55,49.5 r0 top
R109 "4K7" R0201 106.55,50.95 r0 top
R111 "10K" R0201 83,12.9 r225 top
R113 "100R" R0402 90.6,5.4 r45 top
R124 "15K" R0201 82.4,11.5 r45 top
R125 "10K" R0201 89.4,4.2 r45 top
R126 "33K" R0201 91.8,6.6 r45 top
R127 "60K4" R0201 84.4,13.5 r45 top
R130 "1R" R0402 40.5,50.4 r0 top
R135 "698R" R0402 69.8,13.1 r90 top
R136 "910R" R0402 68.95,14.7 r90 top
R137 "2K32" R0402 68.05,14.7 r90 top
R140 "100K" R0201 41.5,32.1 r180 top
R141 "10M" R0201 40.1,28.25 r0 top
R142 "100K" R0201 57.275,48.725 r0 top
R145 "0R" R0402 52.9,30.85 r90 top
R146 "0R" R0402 53.775,30.85 r270 top
R150 "0R" R0402 106.4,50.2 r180 top
R220 "49R9" R0402 88.1,31.4 r180 bottom
R300 "0R" R0402 62.5,50.1 r270 top
R301 "1K" R0402 41.4,51.5 r180 top
R302 "1K" R0402 46.3,51.5 r0 top
R303 "1K" R0402 48.2,51.5 r180 top
R304 "0R" R0402 64.5,50.1 r270 top
R305 "0R" R0402 85.9,31.3 r0 top
R600 "10K" R0201 16.8,55.3 r0 top
R601 "180K" R0201 16.4,53.7 r270 top
R602 "110K" R0201 17,53.7 r90 top
R620 "5K1" R0201 11.9,52.975 r180 top
R621 "5K1" R0201 11.9,51.825 r180 top
R622 "47R" R0402 21.4,28.125 r0 top
R623 "10K" R0201 21.2,27.225 r180 top
R628 "1M" R0402 22.9,26.875 r180 top
R629 "1K" R0201 69.3,26.2 r90 top
R630 "4K7" R0201 52.15,32.5 r270 top
R631 "10K" R0201 51.6,32.5 r90 top
R633 "47K" R0201 50.5,32.5 r270 top
R634 "47K" R0201 49.95,32.5 r90 top
R636 "47K" R0201 47.2,32.5 r90 top
R637 "47K" R0201 46.65,32.5 r90 top
R639 "47K" R0201 48.85,32.5 r90 top
R640 "47K" R0201 48.3,32.5 r90 top
R672 "1K" R0201 24.15,26.525 r90 top
R674 "4K7" R0201 31.25,26.625 r180 top
R675 "3R3" R0402 32.85,26.425 r0 top
R679 "0R" R0402 29.6,26.825 r0 top
R680 "0R" R0402 33.05,25.025 r90 top
R681 "33R" R0402 32.15,25.025 r90 top
R682 "10K" R0201 28.4,24.875 r90 top
R686 "0R" R0402 65.7,27.2 r180 top
R687 "3R3" R0402 61.8,27 r270 top
R688 "4K7" R0201 65.1,25.6 r90 top
R689 "10K" R0201 65.7,25.6 r90 top
R690 "33R" R0402 63.4,24.1 r180 top
R691 "1M" R0402 70,26 r270 top
R700 "10K" R0201 31.425,29.15 r270 top
R701 "4R7" R1206 29.75,34.7 r180 top
R702 "180K" R0201 30.325,29.15 r270 top
R703 "110K" R0201 29.775,29.15 r90 top
R705 "1K" R0201 40.4,36.5 r270 top
R706 "15K" R0201 41,37.2 r90 top
R707 "33K" R0201 44.4,36.8 r270 top
R708 "1M" R0201 44.4,35.475 r90 top
R709 "1K8" R0603 30.35,36.9 r270 top
R710 "1K8" R0603 29.15,36.9 r270 top
R714 "10K" R0201 25.45,28.6 r0 top
R717 "10R" R0402 26.05,37.5 r0 top
R718 "12K" R0603 31.925,40.225 r90 top
R731 "1R" R0402 27.8,48.5 r180 top
R754 "100K" R0201 28.2,29.6 r90 top
R755 "10K" R0201 28.2,30.95 r270 top
R756 "100K" R0201 26.9,28.6 r0 top
R760 "330K" R0201 25.55,35.875 r270 top
R763 "100K" R0201 42.275,47.175 r270 top
R764 "90R9" R0603 24.425,46.875 r0 top
R765 "51K" R0603 23.8,44.9 r90 top
R767 "160R" R0603 23.8,42.45 r90 top
R768 "90R9" R0603 31.5,46.9 r90 top
R769 "51K" R0603 31.5,44.4 r90 top
R771 "51K" R0603 31.5,42.6 r180 top
R792 "1K" R0201 13.975,2.9 r0 top
R793 "10K" R0201 25,8 r0 top
R794 "510K" R0201 16.8,7.95 r180 top
R801 "47K" R0201 67.85,43 r270 top
R805 "33R" R0402 66.85,41.95 r0 top
R807 "4K7" R0201 72.2,37.15 r180 top
R808 "4K7" R0201 72.325,32.625 r180 top
R809 "100K" R0201 54.925,38.425 r270 top
R810 "33R" R0402 53.7,38.725 r0 top
R814 "100K" R0201 66.6,36.4 r90 top
R815 "1K" R0201 66.6,37.75 r270 top
R816 "100K" R0402 72.4,45.7 r180 top
R838 "100K" R0201 61.875,29 r180 top
R839 "10M" R0201 64.1,28.225 r180 top
R840 "100K" R0201 65.4,30.75 r90 top
R841 "1K" R0201 62.7,28.225 r0 top
R850 "100K" R0201 50.9,47.7 r90 top
R851 "100K" R0201 67.9,40.9 r180 top
R852 "100K" R0201 62.5,39.25 r180 top
R853 "100K" R0201 68.075,34.825 r180 top
R882 "220R" R0402 54.85,47.95 r270 top
R900 "2K05" R0201 87.25,54.6 r90 top
R902 "33R" R0402 41.65,41.75 r0 top
R903 "5K76" R0201 10.2,49.6 r180 top
R904 "33R" R0402 41.65,40.875 r0 top
R906 "10K" R0201 54.45,35 r90 top
R907 "4K7" R0201 54.9,49.9 r180 top
R908 "4K7" R0201 54.9,49.3 r180 top
R909 "10K" R0201 54.9,50.5 r180 top
R912 "2K15" R0201 20.5,46.8 r180 top
R919 "1K" R0201 18.6,49.05 r0 top
R920 "1K" R0201 18.6,49.75 r0 top
R928 "100R" R0402 29.85,49.55 r270 top
R930 "1K" R0201 47.85,49.8 r0 top
R931 "1K" R0201 47.85,50.4 r0 top
R950 "100K" R0201 54.9,44.35 r270 top
R951 "100K" R0201 53.525,42.725 r90 top
R952 "100K" R0201 54.075,42.725 r90 top
R981 "100K" R0201 55.05,43.225 r0 top
R982 "10K" R0201 46.05,36.95 r270 top
RP800 "33R" RES_MNR04-8 54.55,40.4 r90 top
RP801 "33R" RES_MNR04-8 66.7,43.55 r90 top
ST701 "2X1_2.54MM" HDR_M254-1X2 2.875,2.08 r90 top locked
SW1 "PTS810" SW_CK_PTS810_SJM_250 107.15,13.325 r0 top
SW100 "PTS810" SW_CK_PTS810_SJM_250 54,13 r0 top locked
SW101 "PTS810" SW_CK_PTS810_SJM_250 42,13 r0 top locked
SW105 "ALPS_SKRH" SW_ALPS_SKRHAAE010 87.05,9 r135 top
SW704 "DPDT_SW_SMD" CK_DPDT_JS202011SCQN 20.9,4.5 r180 top locked
TAB1 "Comment" TAB_V-CUT_L7.0_W2.4 12,0 r180 top locked
TAB2 "Comment" TAB_V-CUT_L7.0_W2.4 60,0 r180 top locked
TAB3 "Comment" TAB_V-CUT_L7.0_W2.4 98,0 r180 top locked
TAB4 "Comment" TAB_V-CUT_L7.0_W2.4 12,60 r0 top locked
TAB5 "Comment" TAB_V-CUT_L7.0_W2.4 60,60 r0 top locked
TAB6 "Comment" TAB_V-CUT_L7.0_W2.4 98,60 r0 top locked
TP150 "TP_SMD" TP_1.0_SMD 38.3,32.3 r270 bottom
TP151 "TP_SMD" TP_1.0_SMD 38.3,27.8 r0 bottom
TP152 "TP_SMD" TP_1.0_SMD 40.8,28.4 r270 bottom
TP153 "TP_SMD" TP_1.0_SMD 47.8,27.6 r270 bottom
TP154 "TP_SMD" TP_1.0_SMD 101.9,14.5 r270 bottom
TP156 "TP_SMD" TP_1.0_SMD 15.3,4.6 r180 bottom
TP157 "TP_SMD" TP_1.0_SMD 81.6,36.5 r270 bottom
TP158 "TP_SMD" TP_1.0_SMD 79.2,35.7 r180 bottom
TP700 "TP_SMD" TP_1.0_SMD 29.9,34.4 r90 bottom
TP701 "TP_SMD" TP_1.0_SMD 28.6,36 r90 bottom
TP703 "TP_SMD" TP_1.0_SMD 28.9,4.7 r180 bottom
TP705 "TP_SMD" TP_1.0_SMD 41.6,36.2 r180 bottom
TP706 "TP_SMD" TP_1.0_SMD 24,48.1 r90 bottom
TP707 "TP_SMD" TP_1.0_SMD 34.2,47.6 r90 bottom
TP708 "TP_SMD" TP_1.0_SMD 48.8,34.8 r90 bottom
TP709 "TP_SMD" TP_1.0_SMD 23.425,2.725 r90 bottom
TP711 "TP_SMD" TP_1.0_SMD 39.7,34.7 r90 bottom
TP712 "TP_SMD" TP_1.0_SMD 39.7,38.8 r90 bottom
TP713 "TP_SMD" TP_1.0_SMD 43.8,36.7 r90 bottom
TP714 "TP_SMD" TP_1.0_SMD 43.2,34.1 r90 bottom
TP715 "TP_SMD" TP_1.0_SMD 23.3,35.4 r180 bottom
TP720 "TP_SMD" TP_1.0_SMD 29.8,29.9 r90 bottom
TP721 "TP_SMD" TP_1.0_SMD 26.8,29.6 r90 bottom
TP923 "TP_SMD" TP_1.0_SMD 46.5,34.2 r90 bottom
TP930 "TP_SMD" TP_1.0_SMD 56.5,32.5 r180 bottom
TPJ600 "TP_SMD" TP_1.0_SMD 14.353,32.302 r90 bottom locked
TPJ606 "TP_SMD" TP_1.0_SMD 97.404,47.202 r90 bottom locked
TPJ607 "TP_SMD" TP_1.0_SMD 66.653,44.101 r90 bottom locked
TPJ608 "TP_SMD" TP_1.0_SMD 34.528,20.527 r90 bottom locked
TPJ611 "TP_SMD" TP_1.0_SMD 10.15,51.3 r180 bottom locked
TPJ612 "TP_SMD" TP_1.0_SMD 10.15,53.85 r180 bottom locked
TPJ613 "TP_SMD" TP_1.0_SMD 12.7,53.85 r180 bottom locked
TPJ614 "TP_SMD" TP_1.0_SMD 7.55,49.8 r180 bottom locked
TPJ650 "TP_SMD" TP_1.0_SMD 108.25,43.248 r90 bottom locked
TPJ651 "TP_SMD" TP_1.0_SMD 108.25,39.7 r90 bottom locked
TPJ652 "TP_SMD" TP_1.0_SMD 61.303,16.102 r90 bottom locked
TPJ653 "TP_SMD" TP_1.0_SMD 51.953,16.102 r90 bottom locked
TPJ811 "TP_SMD" TP_1.0_SMD 77.9,52.7 r180 bottom locked
TPJ812 "TP_SMD" TP_1.0_SMD 81.65,53.45 r180 bottom locked
TPJ814 "TP_SMD" TP_1.0_SMD 84.35,54.3 r180 bottom locked
TPJ817 "TP_SMD" TP_1.0_SMD 102.65,48.35 r180 bottom locked
TPJ818 "TP_SMD" TP_1.0_SMD 71.55,40.95 r180 bottom locked
TPJ820 "TP_SMD" TP_1.0_SMD 80.2,50.95 r180 bottom locked
TPJ900 "TP_SMD" TP_1.0_SMD 41.602,37.9 r90 bottom locked
TPJ901 "TP_SMD" TP_1.0_SMD 44.053,38.55 r90 bottom locked
TPJ902 "TP_SMD" TP_1.0_SMD 24.6,41.4 r180 bottom locked
TPJ905 "TP_SMD" TP_1.0_SMD 54.678,41.126 r90 bottom locked
TPJ908 "TP_SMD" TP_1.0_SMD 43.952,45.601 r90 bottom locked
TPJ909 "TP_SMD" TP_1.0_SMD 42.651,43.427 r90 bottom locked
TPJ910 "TP_SMD" TP_1.0_SMD 48.003,29.65 r90 bottom locked
TPJ911 "TP_SMD" TP_1.0_SMD 45.453,28.85 r90 bottom locked
TPJ912 "TP_SMD" TP_1.0_SMD 50.751,34.225 r90 bottom locked
TPJ913 "TP_SMD" TP_1.0_SMD 50.751,30.501 r90 bottom locked
TPJ950 "TP_SMD" TP_1.0_SMD 24.452,17.1 r90 bottom locked
TPJ953 "TP_SMD" TP_1.0_SMD 42.001,25.251 r90 bottom locked
TPJ954 "TP_SMD" TP_1.0_SMD 43.253,27.501 r90 bottom locked
TPJ955 "TP_SMD" TP_1.0_SMD 44.503,25.251 r90 bottom locked
TPJ956 "TP_SMD" TP_1.0_SMD 52.753,39.251 r90 bottom locked
TPJ957 "TP_SMD" TP_1.0_SMD 51.799,27.599 r180 bottom locked
TPJ958 "TP_SMD" TP_1.0_SMD 53.15,25.45 r180 bottom locked
TPJ959 "TP_SMD" TP_1.0_SMD 54.499,27.599 r90 bottom locked
TPJ960 "TP_SMD" TP_1.0_SMD 53.899,32.598 r90 bottom locked
TPJ961 "TP_SMD" TP_1.0_SMD 53.95,30.05 r180 bottom locked
U1 "EFM8BB52F32I-A-QFN32" QFN32_M050_5.0X5.0_EP_SL_AI 86.6,35 r0 top
U100 "TS3A44159" UQFN16_M040_1.8X2.6_TI_RSV 40.575,30.175 r0 top
U102 "Si7021-A20" DFN6_M100_3.0X3.0_EP_SI7021 111.45,50.05 r90 top
U600 "LP3982ILD-ADJ" WSON8_M050_3.0X2.5_EP_TI_NGM 14.45,54.95 r0 top
U603 "TLV70536" DSBGA4_M040_0.8X0.8_TI_YFP 44.35,32.45 r180 top
U606 "MCP6001T" SC70-5 26.9,25.675 r270 top
U622 "MCP6001T" SC70-5 67.5,25.7 r180 top
U700 "SIP32431" TDFN4_M050_1.6X1.2_EP_VISH 24.5,33.35 r90 top
U701 "LP3982ILD-ADJ" WSON8_M050_3.0X2.5_EP_TI_NGM 31.1,31.5 r270 top
U702 "TS3A4751" QFN14_M040_2.0X2.0_TI_RUC#1 42.7,36.675 r180 top
U703 "LTC6102CDD" DFN8_M050_3.0X3.0_EP_LT_DD 28.85,39.9 r180 top
U704 "AD8656" MSOP8_M065_W3.0 27.65,44.6 r0 top
U800 "74LVC4066" DHVQFN14_M050_2.5X3_EP_NXP 70.9,43.6 r270 top
U802 "74LVC4066" DHVQFN14_M050_2.5X3_EP_NXP 70.9,39.1 r270 top
U803 "74LVC2G125" DSBGA8_M050_0.9X1.9_TI_YZP 61.15,35.575 r0 top
U804 "74LVC2G125" DSBGA8_M050_0.9X1.9_TI_YZP 51.575,38.15 r180 top
U805 "TS3A4751" QFN14_M040_2.0X2.0_TI_RUC#2 64.775,37.07 r90 top
U806 "74LVC4066" DHVQFN14_M050_2.5X3_EP_NXP 70.9,34.6 r270 top
U808 "74LVC8T245" VQFN24_M050_3.5X5.5_EP_TI_RHL 63.4,43.05 r0 top
U809 "74LVC2G125" DSBGA8_M050_0.9X1.9_TI_YZP 52.3,41.675 r180 top
U810 "74LVC4066" DHVQFN14_M050_2.5X3_EP_NXP 70.9,30.1 r270 top
U812 "TS3A4751" QFN14_M040_2.0X2.0_TI_RUC#1 67.1,30.05 r90 top
U860 "74LVC1T45" X2-DFN1010-6_M035_DIODES 51.95,48 r180 top
U861 "74LVC1T45" X2-DFN1010-6_M035_DIODES 67.6,39.9 r90 top
U862 "74LVC1T45" X2-DFN1010-6_M035_DIODES 62.45,38.2 r90 top
U863 "74LVC1T45" X2-DFN1010-6_M035_DIODES 67.7,33.8 r90 top
U900 "EFM32GG12B410F1024GL120-A" BGA120_M050_7.0X7.0_EFM32GGR 46.6,44.5 r180 top locked
U901 "M24C02" TDFN8_M050_2.0X3.0_EP 51.85,50 r0 top
U902 "MX25R8035F" BGA8_M040_1.24X1.75_WLCSP 53.4,34.3 r0 top
U910 "ADC084S021" VSSOP10_M050_W3.0_TI_DGS 48.425,35.025 r0 top
U950 "TS3A4751" QFN14_M040_2.0X2.0_TI_RUC#1 53.225,44.9 r270 top
X900 "48_MHz" X_SSS_DSX211SH_2.05X1.65-4 45.7,49.65 r0 top

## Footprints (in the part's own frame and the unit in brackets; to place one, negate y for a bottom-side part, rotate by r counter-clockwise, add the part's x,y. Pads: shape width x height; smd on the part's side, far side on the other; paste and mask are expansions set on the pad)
ADHESIVE_PAD_25.0X4.0 [mm] "Adhesive for Sharp Display"
  Top Layer keep-out region: 0,4 0,0.001 25,0.001 25,4.001 0,4
  silkscreen extent 0,0 25,4, body extent 0,0 25,4, height 0.2
BAT_HOLD_MPD_BK-912_CR2032 [mil] "MPD Battery Holder BK-912 (for CR2032)"
  rrect20% 110x200 smd: 1(-430,0) 1(430,0)
  round 157.48 smd paste-295.67 mask-82.68: 2(0,0)
  body extent -450,-394 450,394, height 171
BGA8_M040_1.24X1.75_WLCSP [mm] "BGA, 8 pin. U100"
  round 0.21 smd mask+0.05: A1(-0.35,0.4) A3(0.35,0.4) B2(0,0.2) C1(-0.35,0) C3(0.35,0) D2(0,-0.2) E1(-0.35,-0.4) E3(0.35,-0.4)
  body extent -0.63,-0.89 0.63,0.88, height 0.52
BGA120_M050_7.0X7.0_EFM32GGR [mm] "BGA, 120 Leads, Body 7.0x7.0mmx1,30mm, Pitch 0.50mm (191111)"
  round 0.2 smd mask+0.04: A1(-3,3) A2(-2.5,3) A3(-2,3) A4(-1.5,3) A5(-1,3) A6(-0.5,3) A7(0,3) A8(0.5,3) A9(1,3) A10(1.5,3) A11(2,3) A12(2.5,3) A13(3,3) B1(-3,2.5) B2(-2.5,2.5) B3(-2,2.5) B4(-1.5,2.5) B5(-1,2.5) B6(-0.5,2.5) B7(0,2.5) B8(0.5,2.5) B9(1,2.5) B10(1.5,2.5) B11(2,2.5) B12(2.5,2.5) B13(3,2.5) C1(-3,2) C2(-2.5,2) C3(-2,2) C4(-1.5,2) C5(-1,2) C6(-0.5,2) C7(0,2) C8(0.5,2) C9(1,2) C10(1.5,2) C11(2,2) C12(2.5,2) C13(3,2) D1(-3,1.5) D2(-2.5,1.5) D3(-2,1.5) D11(2,1.5) D12(2.5,1.5) D13(3,1.5) E1(-3,1) E2(-2.5,1) E3(-2,1) E11(2,1) E12(2.5,1) E13(3,1) F1(-3,0.5) F2(-2.5,0.5) F3(-2,0.5) F11(2,0.5) F12(2.5,0.5) F13(3,0.5) G1(-3,0) G2(-2.5,0) G3(-2,0) G11(2,0) G12(2.5,0) G13(3,0) H1(-3,-0.5) H2(-2.5,-0.5) H3(-2,-0.5) H11(2,-0.5) H12(2.5,-0.5) H13(3,-0.5) J1(-3,-1) J2(-2.5,-1) J3(-2,-1) J11(2,-1) J12(2.5,-1) J13(3,-1) K1(-3,-1.5) K2(-2.5,-1.5) K3(-2,-1.5) K11(2,-1.5) K12(2.5,-1.5) K13(3,-1.5) L1(-3,-2) L2(-2.5,-2) L3(-2,-2) L4(-1.5,-2) L5(-1,-2) L6(-0.5,-2) L7(0,-2) L8(0.5,-2) L9(1,-2) L10(1.5,-2) L11(2,-2) L12(2.5,-2) L13(3,-2) M1(-3,-2.5) M2(-2.5,-2.5) M3(-2,-2.5) M4(-1.5,-2.5) M5(-1,-2.5) M6(-0.5,-2.5) M7(0,-2.5) M8(0.5,-2.5) M9(1,-2.5) M10(1.5,-2.5) M11(2,-2.5) M12(2.5,-2.5) M13(3,-2.5) N1(-3,-3) N2(-2.5,-3) N3(-2,-3) N4(-1.5,-3) N5(-1,-3) N6(-0.5,-3) N7(0,-3) N8(0.5,-3) N9(1,-3) N10(1.5,-3) N11(2,-3) N12(2.5,-3) N13(3,-3)
  body extent -3.5,-3.5 3.5,3.5, height 1.3
C0201 [mm] "Capacitor, 9291, HiDens (170502)"
  rrect25% 0.36x0.32 smd paste-0.015: 1(-0.275,0) 2(0.275,0)
  Top Layer pour cut-out: -0.075,-0.2 -0.075,0.2 0.075,0.2 0.075,-0.2
  body extent -0.32,-0.13 0.32,0.13, height 0.3
C0402 [mm] "Chip Capacitor, 2-Leads, Body 1.0x0.5mm, IPC High Density (190308)"
  rrect20% 0.5x0.5 smd mask+0.051: 1(-0.5,0) 2(0.5,0)
  Top Layer pour cut-out: -0.225,-0.3 -0.225,0.3 0.225,0.3 0.225,-0.3
  body extent -0.5,-0.25 0.5,0.25, height 0.6
C0603 [mm] "Capacitor, 0603, HiDens (190130)"
  rrect25% 0.8x0.85 smd: 1(-0.7,0) 2(0.7,0)
  Top Layer pour cut-out: -0.275,-0.55 -0.275,0.55 0.275,0.55 0.275,-0.55
  body extent -0.88,-0.48 0.87,0.48, height 0.95
CK_DPDT_JS202011SCQN [mm] "Switch, C & K DPDT JS202011SCQN (190314)"
  rrect50% 1.2x2.5 smd: 1(-2.5,-2.75) 2(0,-2.75) 3(2.5,-2.75) 4(-2.5,2.75) 5(0,2.75) 6(2.5,2.75)
COIL_0402 [mm] "COIL_0402_L (3D from Wurth) (190308)"
  rrect20% 0.55x0.5 smd mask+0.051: 1(-0.525,0) 2(0.525,0)
  body extent -0.5,-0.25 0.5,0.25, height 0.5
COIL_WURTH_CBF_0603 [mm] "COIL_WURTH_CBF_0603 (= L0603_0.8_L) (181031)"
  rrect10% 0.67x0.88 smd: 1(-0.665,0) 2(0.665,0)
  body extent -0.87,-0.48 0.87,0.48, height 0.95
DFN6_M100_3.0X3.0_EP_SI7021 [mm] "(191031)"
  rrect20% 0.85x0.45 smd: 1(-1.45,1) 2(-1.45,0) 3(-1.45,-1) 4(1.45,-1) 5(1.45,0) 6(1.45,1)
  rrect20% 1.6x2.5 smd: 7(0,0)
  body extent -1.5,-1.5 1.5,1.5, height 1.22
DFN8_M050_3.0X3.0_EP_LT_DD [mm] "DFN 8 Lead, Pitch 0.5, 3.0x3.0x0.75 Exposed Pad, Linear Tech (171004)"
  rrect50% 0.7x0.25 smd paste-0.025 mask+0.07: 1(-1.4,0.75) 2(-1.4,0.25) 3(-1.4,-0.25) 4(-1.4,-0.75) 5(1.4,-0.75) 6(1.4,-0.25) 7(1.4,0.25) 8(1.4,0.75)
  rect 1x1.8 smd paste-1 mask+0: 9(0,0)
  Top Layer region: 0.825,1.2 -0.693,1.2 -0.825,1.095 -0.825,-1.2 0.825,-1.2
  body extent -1.56,-1.55 1.56,1.55, height 0.8
DFN2111-7_M050_1.2X2.1_NXP [mm] "DFN2111-7 NXP Pitch 035 1.2x2.1x0.5, NXP (190312)"
  rrect20% 0.53x0.19 smd mask+0.05: 1(-0.415,0.75) 2(-0.415,0.25) 3(-0.415,-0.25) 4(-0.415,-0.75) 5(0.415,-0.5) 6(0.415,0) 7(0.415,0.5)
  body extent -0.6,-1.05 0.6,1.05, height 0.51
DHVQFN14_M050_2.5X3_EP_NXP [mm] "DHVQFN, 14 Leads, 2.5x3.0x0.85, Pitch 0.50, Thermal Pad 1.0x1.5 (190314)"
  oval 0.3x0.7 smd: 1(-0.25,1.45) 7(-0.25,-1.45) 8(0.25,-1.45) 14(0.25,1.45)
  oval 0.7x0.3 smd: 2(-1.2,1) 3(-1.2,0.5) 4(-1.2,0) 5(-1.2,-0.5) 6(-1.2,-1) 9(1.2,-1) 10(1.2,-0.5) 11(1.2,0) 12(1.2,0.5) 13(1.2,1)
  rrect10% 1x1.5 smd: 17(0,0)
  body extent -1.25,-1.5 1.25,1.5, height 1.1
DSBGA4_M040_0.8X0.8_TI_YFP [mm] "DS-BGA, 4 Leads, Body 0.8x0.8 H:0.5, Pitch 0.40"
  round 0.23 smd mask+0.04: A1(-0.2,0.2) A2(0.2,0.2) B1(-0.2,-0.2) B2(0.2,-0.2)
  body extent -0.4,-0.4 0.4,0.4, height 0.51
DSBGA8_M050_0.9X1.9_TI_YZP [mm] "DS-BGA, 8 Leads, Body 0.9x1.9 H:0.5, Pitch 0.50"
  round 0.23 smd: A1(-0.25,0.75) A2(0.25,0.75) B1(-0.25,0.25) B2(0.25,0.25) C1(-0.25,-0.25) C2(0.25,-0.25) D1(-0.25,-0.75) D2(0.25,-0.75)
  body extent -0.45,-0.95 0.45,0.95, height 0.51
FCI_10137065_USB-C_RCPT [mm] "FCI AMPHENOL 10137065 USB-C Receptacle (Slot PinInPaste) (180404)"
  oval 1.3x2.6 hole 0.7 slot 2 at 90 deg: 25(-4.32,-3.05) 26(4.32,-3.05)
  oval 1.3x2.6 on Top Paste: 25(-4.32,-3.05) 26(4.32,-3.05)
  oval 1.2x2.3 hole 0.6 slot 1.9 at 90 deg: 27(-4.32,2) 28(4.32,2)
  oval 1.2x2.3 on Top Paste: 27(-4.32,2) 28(4.32,2)
  oval 1.347x1.1 hole 0.6 slot 1.247 at 0 deg: 27(-4.025,1.4) 28(4.025,1.4)
  oval 1.347x1.1 on Top Paste: 27(-4.025,1.4) 28(4.025,1.4)
  rrect20% 0.27x0.9 smd mask+0.076: A1(-2.625,2.7) A2(-2.125,2.7) A3(-1.625,2.7) A4(-1.125,2.7) A5(-0.625,2.7) A6(-0.125,2.7) A7(0.375,2.7) A8(0.875,2.7) A9(1.375,2.7) A10(1.875,2.7) A11(2.375,2.7) A12(2.875,2.7)
  rrect20% 0.27x0.8 smd mask+0.076: B1(2.625,1.1) B2(2.125,1.1) B3(1.625,1.1) B4(1.125,1.1) B5(0.625,1.1) B6(0.125,1.1) B7(-0.375,1.1) B8(-0.875,1.1) B9(-1.375,1.1) B10(-1.875,1.1) B11(-2.375,1.1) B12(-2.875,1.1)
  round 0 hole 0.6 unplated mask+0.102: M1(-3.6,0)
  round 0 hole 0.5 slot 0.85 at 0 deg unplated mask+0.102: M2(3.6,0)
  Top Layer keep-out region: -3.9,-4.85 3.9,-4.85 3.9,0.4 -3.9,0.4
  body extent -4.47,-5.3 4.47,2.85, height 3.14
HDR_M254-1X2 [mm] "Connector; Header; 2 Position (170508)"
  round 1.6 hole 1: 1(0,0) 2(2.54,0)
  body extent -1.07,-1.17 3.61,1.17, height 8.12
HDR_M254-2X16 [mm] "Connector; Header; 2x16 Position, 2.54mm (190808)"
  round 1.6 hole 1: 1(-19.05,-1.27) 2(-19.05,1.27) 3(-16.51,-1.27) 4(-16.51,1.27) 5(-13.97,-1.27) 6(-13.97,1.27) 7(-11.43,-1.27) 8(-11.43,1.27) 9(-8.89,-1.27) 10(-8.89,1.27) 11(-6.35,-1.27) 12(-6.35,1.27) 13(-3.81,-1.27) 14(-3.81,1.27) 15(-1.27,-1.27) 16(-1.27,1.27) 17(1.27,-1.27) 18(1.27,1.27) 19(3.81,-1.27) 20(3.81,1.27) 21(6.35,-1.27) 22(6.35,1.27) 23(8.89,-1.27) 24(8.89,1.27) 25(11.43,-1.27) 26(11.43,1.27) 27(13.97,-1.27) 28(13.97,1.27) 29(16.51,-1.27) 30(16.51,1.27) 31(19.05,-1.27) 32(19.05,1.27)
HDR_SULLINS_M127_PEG-2X10 [mil] "Sullins, GRPB102VQS (180319)"
  rrect50% 30x87 smd: 1(-25,-72.5) 2(-25,72.5) 3(25,-72.5) 4(25,72.5) 5(75,-72.5) 6(75,72.5) 7(125,-72.5) 8(125,72.5) 9(175,-72.5) 10(175,72.5) 11(225,-72.5) 12(225,72.5) 13(275,-72.5) 14(275,72.5) 15(325,-72.5) 16(325,72.5) 17(375,-72.5) 18(375,72.5) 19(425,-72.5) 20(425,72.5)
  round 0 hole 39.37 mask+3.94: M1(0,0) M2(400,0)
  body extent -50,-100 450,101, height 197
HOLE_3.0_5.0_PL [mm] "Hole 3.0 mm, Plated (171122)"
  round 5 hole 3: 1(0,0)
HOLE_3.0_NPL [mm] "HOLE_3.0_NPL (170815)"
  round 0 hole 3 unplated mask+0.2: 1(0,0)
  body extent -1.5,-1.5 1.5,1.5
HRS_U.FL-R-SMT_123 [mm] "COAX_HIROSE_U.FL_CL331-0471 (170228)"
  rrect20% 1.05x1.1 smd mask+0.051: 1(0,-1.6)
  rrect20% 1.05x2.25 smd mask+0.051: 2(1.5,0) 3(-1.5,0)
  Top Layer pour cut-out: 0.85,-0.9 -0.85,-0.9 -0.85,-0.9 -0.85,1.2 0.85,1.2 0.85,1.2
  body extent -1.3,-1.3 1.3,1.55, height 0.9
LABEL_4CORNERS_19.0X6.0 [mm]
  silkscreen extent -9.5,-3 9.5,3
LABEL_P101_PIN_TABLE_SL [mm]
  silkscreen extent -2.4,-12.5 2.4,12.5
LED_0402 [mm] "Chip Diode, 2-Leads, Body 1.00x0.50mm, IPC High Density (170127)"
  rrect10% 0.45x0.6 smd: 1(-0.45,0) 2(0.45,0)
  body extent -0.55,-0.33 0.55,0.33, height 0.25
LED_0402_CAT2 [mm] "(200921)"
  rrect10% 0.45x0.6 smd: 1(-0.45,0) 2(0.45,0)
  body extent -0.55,-0.33 0.55,0.33, height 0.25
LED_AVAGO_HSMF-C165-4 [mm] "LED (dual) Avago HSMF-C165 Grn+Red 1.6x0.8x0.5 (200226)"
  rrect20% 0.7x0.4 smd: 1(-0.65,-0.35) 2(-0.65,0.35) 3(0.65,0.35) 4(0.65,-0.35)
  body extent -0.8,-0.4 0.8,0.4, height 0.52
LED_LUMEX_SML-LX0404-4 [mm] "LED, LUMEX, SML LX0404 1.0x1.0x0.25 NB! Pin numbering (180111)"
  rrect25% 0.45x0.45 smd mask+0.05: 1(-0.425,-0.425) 2(-0.425,0.425) 3(0.425,0.425) 4(0.425,-0.425)
  body extent -0.5,-0.5 0.5,0.5, height 0.31
LOGO_BEE_H7.0 [mm] "Silicon Labs Logo Bee (210415)"
  silkscreen extent -3.58,0 3.61,6.92
LOGO_SEGGER_10.0X5.0_SM [mm] "Logo, Segger 10.0x5.0, Top Solder + M19 + Top Overlay"
LOGO_SILABS_W14.0_SILK [mm] "LOGO_SILABS_W14.0 SILKSCREEN ONLY"
  silkscreen extent 0.03,0 13.99,6.83
LOGO_SILABS_W18.0 [mm]
  silkscreen extent 0.02,0.02 16.98,8.32
MSOP8_M065_W3.0 [mm] "MSOP, 8-Leads, Body 3.0x3.0mm, Pitch 0.65mm (170921)"
  rrect20% 0.889x0.42 smd mask+0.048: 1(-2.105,0.975) 2(-2.105,0.325) 3(-2.105,-0.325) 4(-2.105,-0.975) 5(2.106,-0.975) 6(2.106,-0.325) 7(2.106,0.325) 8(2.106,0.975)
  body extent -1.55,-1.55 1.55,1.55, height 1.11
OLED_LS013B7DH03 [mm] "LS013B7DH03 (200526)"
  body extent -13.3,-18.6 13.3,13.23, height 3.8
POWERPAK_SC70-6 [mm] "POWERPAK SC70-6 HiDens (Vishay) (170926)"
  rrect10% 0.325x0.3 smd paste-0.025 mask+0.07: 1(-0.913,0.65) 2(-0.913,0) 3(-0.913,-0.65) 4(0.913,-0.65) 5(0.913,0) 6(0.913,0.65)
  rrect10% 0.95x0.613 smd paste-0.025 mask+0.07: 7(0,0.466) 8(0,-0.466)
  body extent -1.02,-1.02 1.02,1.05, height 0.8
QFN14_M040_2.0X2.0_TI_RUC#1 [mm] "QFN 14 Leads, Pitch 0.4 mm, 2.0 x 2.0 H: 0.37, TI: RUC (180613)"
  rrect20% 0.68x0.2 smd paste+0 mask+0.05: 1(-0.885,0.8) 2(-0.885,0.4) 3(-0.885,0) 4(-0.885,-0.4) 5(-0.885,-0.8) 8(0.885,-0.8) 9(0.885,-0.4) 10(0.885,0) 11(0.885,0.4) 12(0.885,0.8)
  rrect20% 0.2x0.68 smd paste+0 mask+0.05: 6(-0.2,-0.885) 7(0.2,-0.885) 13(0.2,0.885) 14(-0.2,0.885)
  body extent -1,-1 1,1, height 0.41
QFN14_M040_2.0X2.0_TI_RUC#2 [mm] "QFN 14 Leads, Pitch 0.4 mm, 2.0 x 2.0 H: 0.37, TI: RUC (180613)"
  rrect20% 0.68x0.2 smd: 1(-0.885,0.8) 2(-0.885,0.4) 3(-0.885,0) 4(-0.885,-0.4) 5(-0.885,-0.8) 8(0.885,-0.8) 9(0.885,-0.4) 10(0.885,0) 11(0.885,0.4) 12(0.885,0.8)
  rrect20% 0.2x0.68 smd: 6(-0.2,-0.885) 7(0.2,-0.885) 13(0.2,0.885) 14(-0.2,0.885)
  body extent -1,-1 1,1, height 0.41
QFN32_M050_5.0X5.0_EP_SL_AI [mm] "QFN32, Pitch 0.50 5.0x5.0 H1.0 (210322)"
  rrect20% 0.85x0.3 smd: 1(-2.45,1.75) 2(-2.45,1.25) 3(-2.45,0.75) 4(-2.45,0.25) 5(-2.45,-0.25) 6(-2.45,-0.75) 7(-2.45,-1.25) 8(-2.45,-1.75) 17(2.45,-1.75) 18(2.45,-1.25) 19(2.45,-0.75) 20(2.45,-0.25) 21(2.45,0.25) 22(2.45,0.75) 23(2.45,1.25) 24(2.45,1.75)
  rrect20% 0.3x0.85 smd: 9(-1.75,-2.45) 10(-1.25,-2.45) 11(-0.75,-2.45) 12(-0.25,-2.45) 13(0.25,-2.45) 14(0.75,-2.45) 15(1.25,-2.45) 16(1.75,-2.45) 25(1.75,2.45) 26(1.25,2.45) 27(0.75,2.45) 28(0.25,2.45) 29(-0.25,2.45) 30(-0.75,2.45) 31(-1.25,2.45) 32(-1.75,2.45)
  rrect5% 3.5x3.5 smd paste-100: 33(0,0)
  body extent -2.5,-2.5 2.5,2.5, height 1.01
R0201 [mm] "Resistor (Chip2PinSM127P600-8N) (170921)"
  rrect25% 0.34x0.32 smd: 1(-0.3,0) 2(0.3,0)
  Top Layer pour cut-out: -0.1,-0.2 -0.1,0.2 0.1,0.2 0.1,-0.2
  body extent -0.32,-0.13 0.32,0.13, height 0.3
R0402 [mm] "Chip Resistor, 2-Leads, Body 1.0x0.5mm, HiDens (190308)"
  rrect20% 0.6x0.6 smd mask+0.051: 1(-0.45,0) 2(0.45,0)
  Top Layer pour cut-out: -0.125,-0.3 -0.125,0.3 0.125,0.3 0.125,-0.3
  body extent -0.5,-0.25 0.5,0.25, height 0.6
R0603 [mm] "Chip Resistor, 0603, HiDens (190130)"
  rrect25% 0.85x0.9 smd: 1(-0.7,0) 2(0.7,0)
  Top Layer pour cut-out: -0.25,-0.575 -0.25,0.575 0.25,0.575 0.25,-0.575
  body extent -0.88,-0.48 0.87,0.48, height 0.95
R1206 [mm] "Resistor, 1206, HiDens (191114)"
  rrect25% 0.85x1.65 smd paste-0.04 mask+0.07: 1(-1.425,0) 2(1.425,0)
  body extent -1.6,-0.8 1.6,0.8, height 1
RES_MNR04-8 [mm] "Resistor Array, ROHM MNR04 8-Pin 2.0x1.0x0.35 (!80615)"
  rrect20% 0.4x0.5 smd: 1(-0.75,-0.45) 4(0.75,-0.45) 5(0.75,0.45) 8(-0.75,0.45)
  rrect20% 0.3x0.5 smd: 2(-0.25,-0.45) 3(0.25,-0.45) 6(0.25,0.45) 7(-0.25,0.45)
  body extent -1,-0.4 1,0.4, height 0.5
SC70-5 [mm] "SC70-5 = SOT353, HiDens (170511)"
  rrect25% 0.6x0.4 smd paste-0.03 mask+0.05: 1(-0.95,0.65) 2(-0.95,0) 3(-0.95,-0.65) 4(0.95,-0.65) 5(0.95,0.65)
  body extent -1.12,-0.97 1.16,1.03, height 0.95
SC70_123 [mm] "SC70 = SOT323_123, HiDens (170509)"
  rrect25% 0.75x0.4 smd: 1(-1,0.65) 2(-1,-0.65) 3(1,0)
  body extent -1.1,-1 1.1,1, height 0.9
SOT563 [mm] "SOT563 (_M050_W1.2_), 6-Leads, Body 1.60x1.20, Pitch 0.5, HiDens (170926)"
  rrect25% 0.6x0.3 smd: 1(-0.65,0.5) 2(-0.65,0) 3(-0.65,-0.5) 4(0.65,-0.5) 5(0.65,0) 6(0.65,0.5)
  body extent -0.65,-0.85 0.65,0.85, height 0.6
SOT563_DIODES [mm] "SOT563 (_M050_W1.2_), 6-Leads, Body 1.60x1.20, Pitch 0.5, HiDens (170926)"
  rrect25% 0.5x0.375 smd: 1(-0.85,0.5) 2(-0.85,0) 3(-0.85,-0.5) 4(0.85,-0.5) 5(0.85,0) 6(0.85,0.5)
  body extent -0.66,-0.85 0.65,0.85, height 0.6
SW_ALPS_SKRHAAE010 [mm] "Switch, ALPS / ALPINE (200615)"
  rrect20% 1.35x1 smd: 1(-3.575,1.425) 2(-3.575,0) 3(-3.575,-1.425) 4(3.575,1.425) 5(3.575,0) 6(3.575,-1.425)
  rrect20% 2x1.8 smd: 7(0,4.05) 8(0,-4.05)
  round 0 hole 0.75 mask+0.102: M1(0,1.9)
  round 0 hole 1.05 mask+0.102: M2(0,-1.9)
  body extent -3.74,-3.75 3.74,3.75, height 5
SW_CK_PTS810_SJM_250 [mm] "Switch C&K PTS810_SJM_250 (grey button) (180319)"
  rrect20% 1.05x0.65 smd: 1(-2.075,1.075) 2(2.075,1.075) 3(-2.075,-1.075) 4(2.075,-1.075)
  body extent -2.29,-1.6 2.29,1.6, height 2.5
TAB_V-CUT_L7.0_W2.4 [mm] "TAB V_CUT, Length 7.0, Width 2.4"
TDFN4_M050_1.6X1.2_EP_VISH [mm] "TDFN, 4-Leads, Body 1.60x1.20mm, IPC HiDens (180111)"
  rrect10% 0.55x0.3 smd: 1(-0.725,0.25) 2(-0.725,-0.25) 3(0.725,-0.25) 4(0.725,0.25)
  rrect10% 0.5x0.86 smd paste-0.05: 5(0,0)
  body extent -0.8,-0.6 0.8,0.6, height 0.61
TDFN8_M050_2.0X3.0_EP [mm] "TDFN8_M050_2.0x3.0_EP (170921)"
  rrect20% 0.75x0.3 smd: 1(-1.45,0.75) 2(-1.45,0.25) 3(-1.45,-0.25) 4(-1.45,-0.75) 5(1.45,-0.75) 6(1.45,-0.25) 7(1.45,0.25) 8(1.45,0.75)
  rrect10% 1.5x1.4 smd: 9(0,0)
  body extent -1.5,-1 1.5,1, height 1.01
TP_1.0_SMD [mm] "Test Point, 1.0 mm, SMD (170509)"
  round 1 smd paste-0.501: 1(0,0)
  body extent -0.5,-0.5 0.5,0.5, height 0.04
UQFN16_M040_1.8X2.6_TI_RSV [mm] "UQFN 16 Leads, Pitch 0.4, 1.9x2.6x0.5, TI: RSV (190816)"
  rrect20% 0.7x0.2 smd paste+0 mask+0.05: 1(-0.75,0.6)
  rrect20% 0.6x0.2 smd paste+0 mask+0.05: 2(-0.8,0.2) 3(-0.8,-0.2) 4(-0.8,-0.6) 9(0.8,-0.6) 10(0.8,-0.2) 11(0.8,0.2) 12(0.8,0.6)
  rrect20% 0.2x0.6 smd paste+0 mask+0.05: 5(-0.6,-1.2) 6(-0.2,-1.2) 7(0.2,-1.2) 8(0.6,-1.2) 13(0.6,1.2) 14(0.2,1.2) 15(-0.2,1.2) 16(-0.6,1.2)
  body extent -0.9,-1.3 0.9,1.3, height 0.56
VQFN24_M050_3.5X5.5_EP_TI_RHL [mm] "VQFN 24 Leads, Pitch 0.50 3.5x5.0x0.9, TI: RHL (171011)"
  rrect20% 0.28x0.99 smd: 1(-0.75,2.795) 12(-0.75,-2.795) 13(0.75,-2.795) 24(0.75,2.795)
  rrect20% 0.99x0.28 smd: 2(-1.795,2.25) 3(-1.795,1.75) 4(-1.795,1.25) 5(-1.795,0.75) 6(-1.795,0.25) 7(-1.795,-0.25) 8(-1.795,-0.75) 9(-1.795,-1.25) 10(-1.795,-1.75) 11(-1.795,-2.25) 14(1.795,-2.25) 15(1.795,-1.75) 16(1.795,-1.25) 17(1.795,-0.75) 18(1.795,-0.25) 19(1.795,0.25) 20(1.795,0.75) 21(1.795,1.25) 22(1.795,1.75) 23(1.795,2.25)
  rrect5% 2.05x4.05 smd: 25(0,0)
  Top Layer region: 0.39,-3.26 0.39,-2 -0.39,-2 -0.39,-3.26 -0.388,-3.272 -0.381,-3.281 -0.372,-3.288 -0.36,-3.29 -0.36,-3.29 -0.14,-3.29 -0.129,-3.288 -0.119,-3.281 -0.112,-3.272 -0.11,-3.26 -0.11,-3.26 -0.11,-2.32 -0.108,-2.312 -0.104,-2.306 -0.098,-2.301 -0.09,-2.3 -0.09,-2.3 0.09,-2.3 0.1,-2.303 0.107,-2.31 0.11,-2.32 0.11,-2.32 0.11,-3.26 0.112,-3.272 0.119,-3.281 0.129,-3.288 0.14,-3.29 0.14,-3.29 0.36,-3.29 0.372,-3.288 0.381,-3.281 0.388,-3.271 0.39,-3.26
  Top Layer region: -0.39,3.26 -0.39,2 0.39,2 0.39,3.26 0.388,3.272 0.381,3.281 0.372,3.288 0.36,3.29 0.36,3.29 0.14,3.29 0.129,3.288 0.119,3.281 0.112,3.272 0.11,3.26 0.11,3.26 0.11,2.32 0.108,2.312 0.104,2.306 0.098,2.301 0.09,2.3 0.09,2.3 -0.09,2.3 -0.1,2.303 -0.107,2.31 -0.11,2.32 -0.11,2.32 -0.11,3.26 -0.112,3.272 -0.119,3.281 -0.129,3.288 -0.14,3.29 -0.14,3.29 -0.36,3.29 -0.372,3.288 -0.381,3.281 -0.388,3.271 -0.39,3.26
  body extent -1.75,-2.75 1.75,2.75, height 1
VSSOP10_M050_W3.0_TI_DGS [mm] "VSSOP, 10-Leads, 3.0x3.0x(max1.1), Pitch 0.50mm, (TI: DGS) (190816)"
  rrect20% 1.45x0.3 smd: 1(-2.2,1) 2(-2.2,0.5) 3(-2.2,0) 4(-2.2,-0.5) 5(-2.2,-1) 6(2.2,-1) 7(2.2,-0.5) 8(2.2,0) 9(2.2,0.5) 10(2.2,1)
  body extent -1.5,-1.5 1.5,1.5, height 1.1
WCON_1125B-1210_HOR_PEG-2X10 [mm] "WCON 2x10 header (201021)"
  rrect50% 1.27x3.175 smd: 1(-1.27,4.24) 2(-1.27,8.43) 3(1.27,4.24) 4(1.27,8.43) 5(3.81,4.24) 6(3.81,8.43) 7(6.35,4.24) 8(6.35,8.43) 9(8.89,4.24) 10(8.89,8.43) 11(11.43,4.24) 12(11.43,8.43) 13(13.97,4.24) 14(13.97,8.43) 15(16.51,4.24) 16(16.51,8.43) 17(19.05,4.24) 18(19.05,8.43) 19(21.59,4.24) 20(21.59,8.43)
  round 0 hole 1.9 unplated paste+0.91 mask+0.1: M1(0,0) M2(20.32,0)
  body extent -2.54,-7.11 22.86,9.15, height 6.1
WCON_3132_HDR_M127_SMD-2X10 [mm] "WCON_3132_HDR_M127_SMD-2X10 (210215)"
  rrect50% 0.74x2.4 smd: 1(-5.715,-1.95) 2(-5.715,1.95) 3(-4.445,-1.95) 4(-4.445,1.95) 5(-3.175,-1.95) 6(-3.175,1.95) 7(-1.905,-1.95) 8(-1.905,1.95) 9(-0.635,-1.95) 10(-0.635,1.95) 11(0.635,-1.95) 12(0.635,1.95) 13(1.905,-1.95) 14(1.905,1.95) 15(3.175,-1.95) 16(3.175,1.95) 17(4.445,-1.95) 18(4.445,1.95) 19(5.715,-1.95) 20(5.715,1.95)
  body extent -6.35,-4.53 6.35,2.84, height 6.58
WCON_5142_FPC_0.5-10 [mm] "WCON  5142-XXRZUWWR01 (3D IS FROM MOL 5450) (201013)"
  rrect50% 0.3x1.25 smd mask+0.076: 1(0,0) 2(0.5,0) 3(1,0) 4(1.5,0) 5(2,0) 6(2.5,0) 7(3,0) 8(3.5,0) 9(4,0) 10(4.5,0)
  rrect5% 2x2.5 smd: 11(-1.69,-2.625) 12(6.19,-2.625)
  body extent -2.85,-5.05 7.35,-0.05, height 1.2
WSON8_M050_3.0X2.5_EP_TI_NGM [mm] "WSON8, Pitch 0.5, 3.0x2.5x0.8 EP TI: NGM (181205)"
  rrect20% 0.5x0.25 smd mask+0.051: 1(-1.15,0.75) 2(-1.15,0.25) 3(-1.15,-0.25) 4(-1.15,-0.75) 5(1.15,-0.75) 6(1.15,-0.25) 7(1.15,0.25) 8(1.15,0.75)
  rrect10% 1.2x1.5 smd mask+0.051: 9(0,0)
  body extent -1.5,-1.25 1.5,1.25, height 0.8
X2-DFN1006-2 [mm] "Diodes case X2-DFN1006-2 part DESD5V0S1BLD (201012)"
  rrect20% 0.4x0.7 smd mask+0.04: 1(-0.35,0) 2(0.35,0)
  body extent -0.5,-0.3 0.5,0.3, height 0.41
X2-DFN1010-6_M035_DIODES [mm] "X2-DFN1010-6 Pitch 0.35 1.0x1.0x0.4, Diodes Inc (181025)"
  rrect20% 0.55x0.2 smd mask+0.04: 1(-0.35,0.35) 2(-0.35,0) 3(-0.35,-0.35) 4(0.35,-0.35) 5(0.35,0) 6(0.35,0.35)
  body extent -0.5,-0.5 0.5,0.5, height 0.41
X2-DFN2015-3_DIODES [mm] "X2-DFN2015-3 DIODES (181204)"
  rrect10% 0.5x0.31 smd mask+0.07: 1(-0.9,0.5) 2(-0.9,-0.5)
  rrect10% 0.75x0.31 smd mask+0.07: 3(0.775,0)
  Top Layer region: 0.5,0.55 0.5,-0.55 0.487,-0.6 0.45,-0.637 0.4,-0.65 0.4,-0.65 -0.4,-0.65 -0.45,-0.637 -0.487,-0.6 -0.5,-0.55 -0.5,-0.55 -0.5,0.55 -0.487,0.6 -0.45,0.637 -0.4,0.65 -0.4,0.65 0.4,0.65 0.45,0.637 0.487,0.6 0.5,0.55
  body extent -1.04,-0.79 1.04,0.79, height 0.4
X_SSS_DSX211SH_2.05X1.65-4 [mm] "X_SSS_DSX211SH_2.05X1.65-4"
  rrect20% 0.9x0.8 smd: 1(-0.7,-0.55) 2(0.7,-0.55) 3(0.7,0.55) 4(-0.7,0.55)
  body extent -1.07,-0.87 1.07,0.87, height 0.51

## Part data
LED900: library part Yellow
LED901: library part Blue

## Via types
v1: diameter 0.508, hole 0.25, Top Layer to Bottom Layer, tented both sides, 834 vias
